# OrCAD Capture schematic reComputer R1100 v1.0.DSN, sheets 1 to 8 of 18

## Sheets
1 02 Block Diagram: rev: v1.0
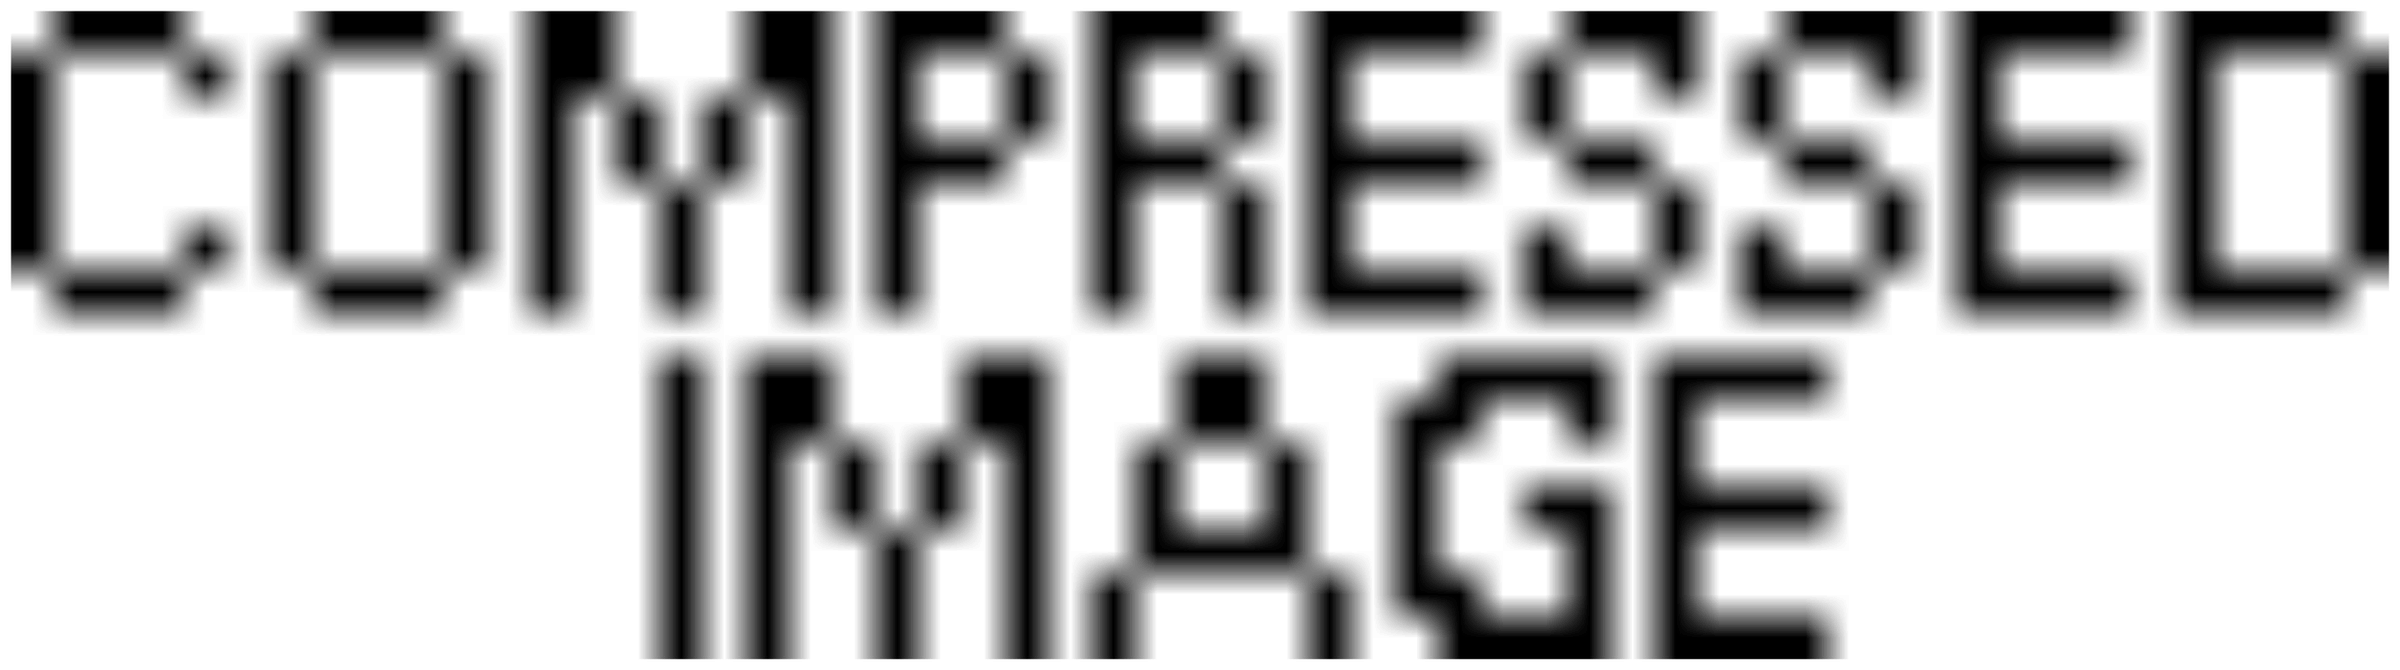
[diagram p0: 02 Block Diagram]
2 03 Power Block Diagram
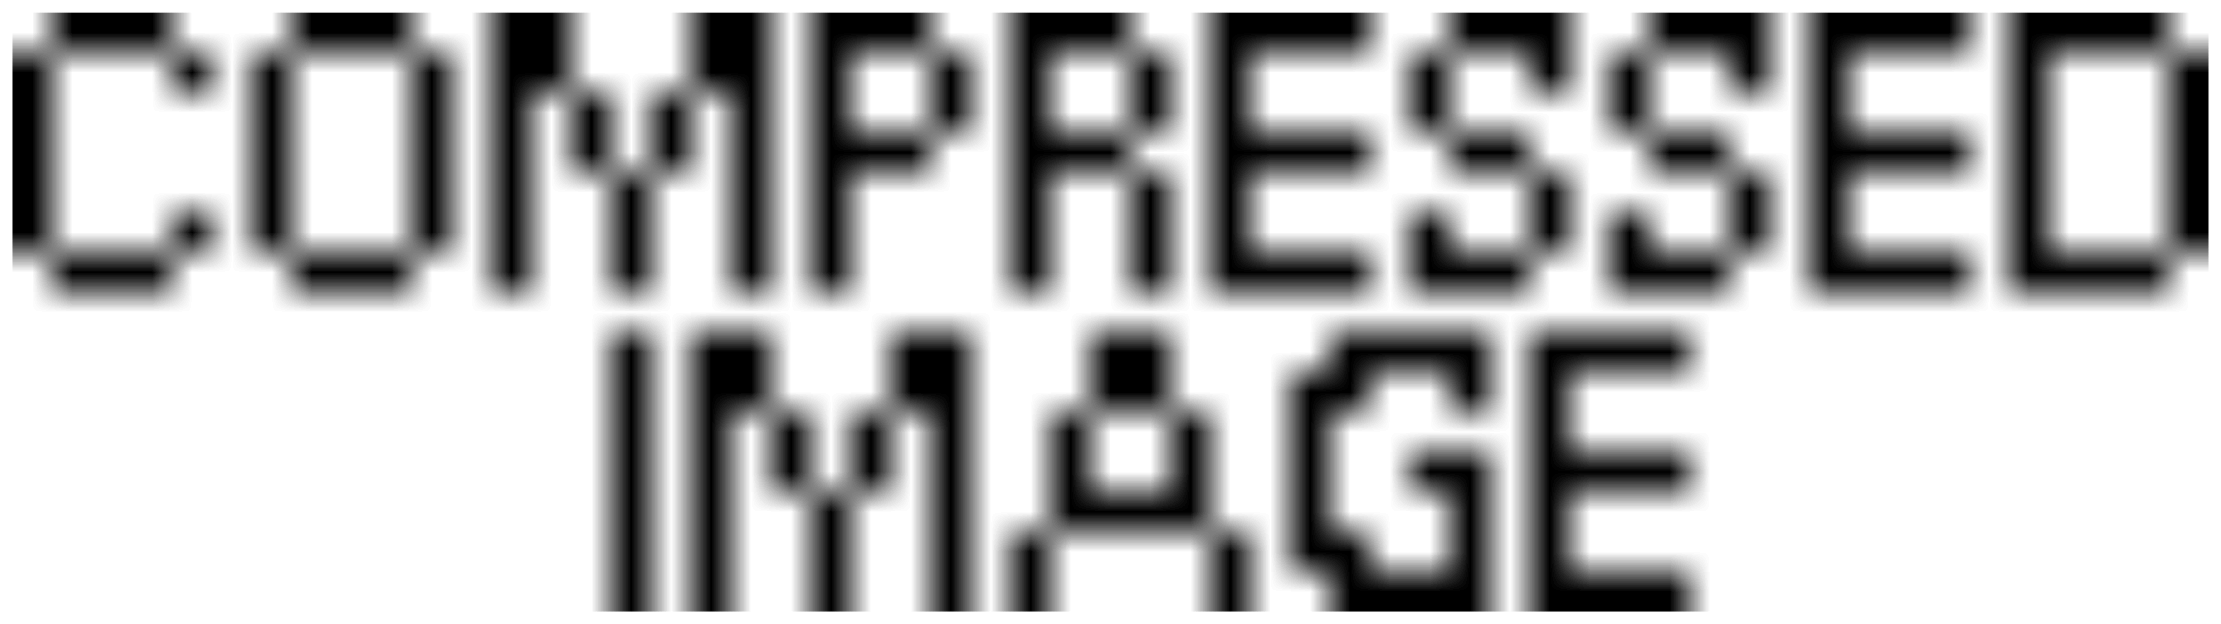
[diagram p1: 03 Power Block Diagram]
3 04 IIC TREE
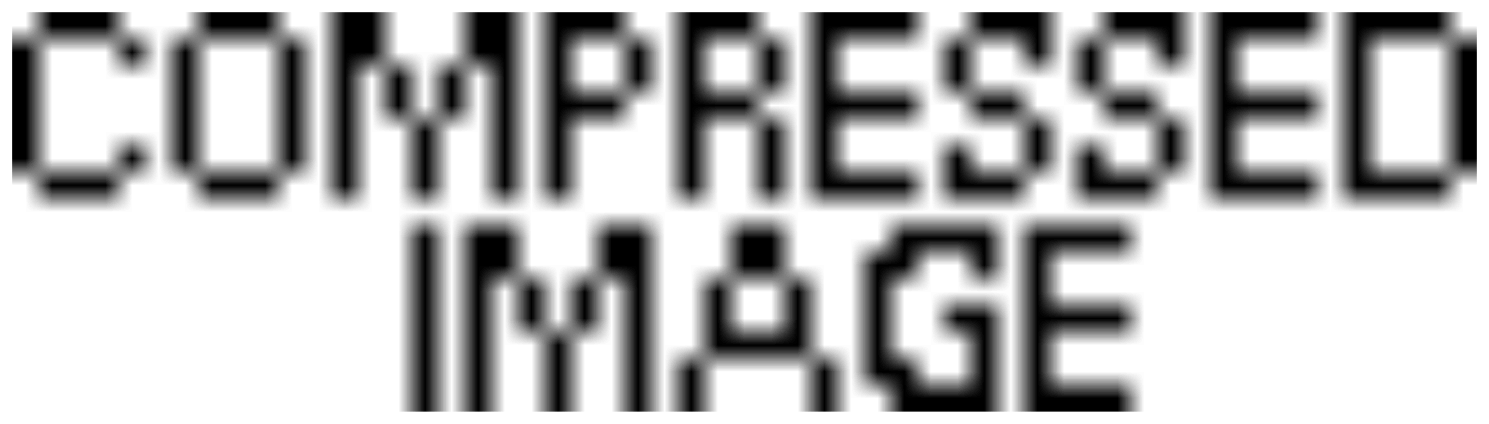
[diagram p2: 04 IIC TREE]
4 05 Power IN: size A3
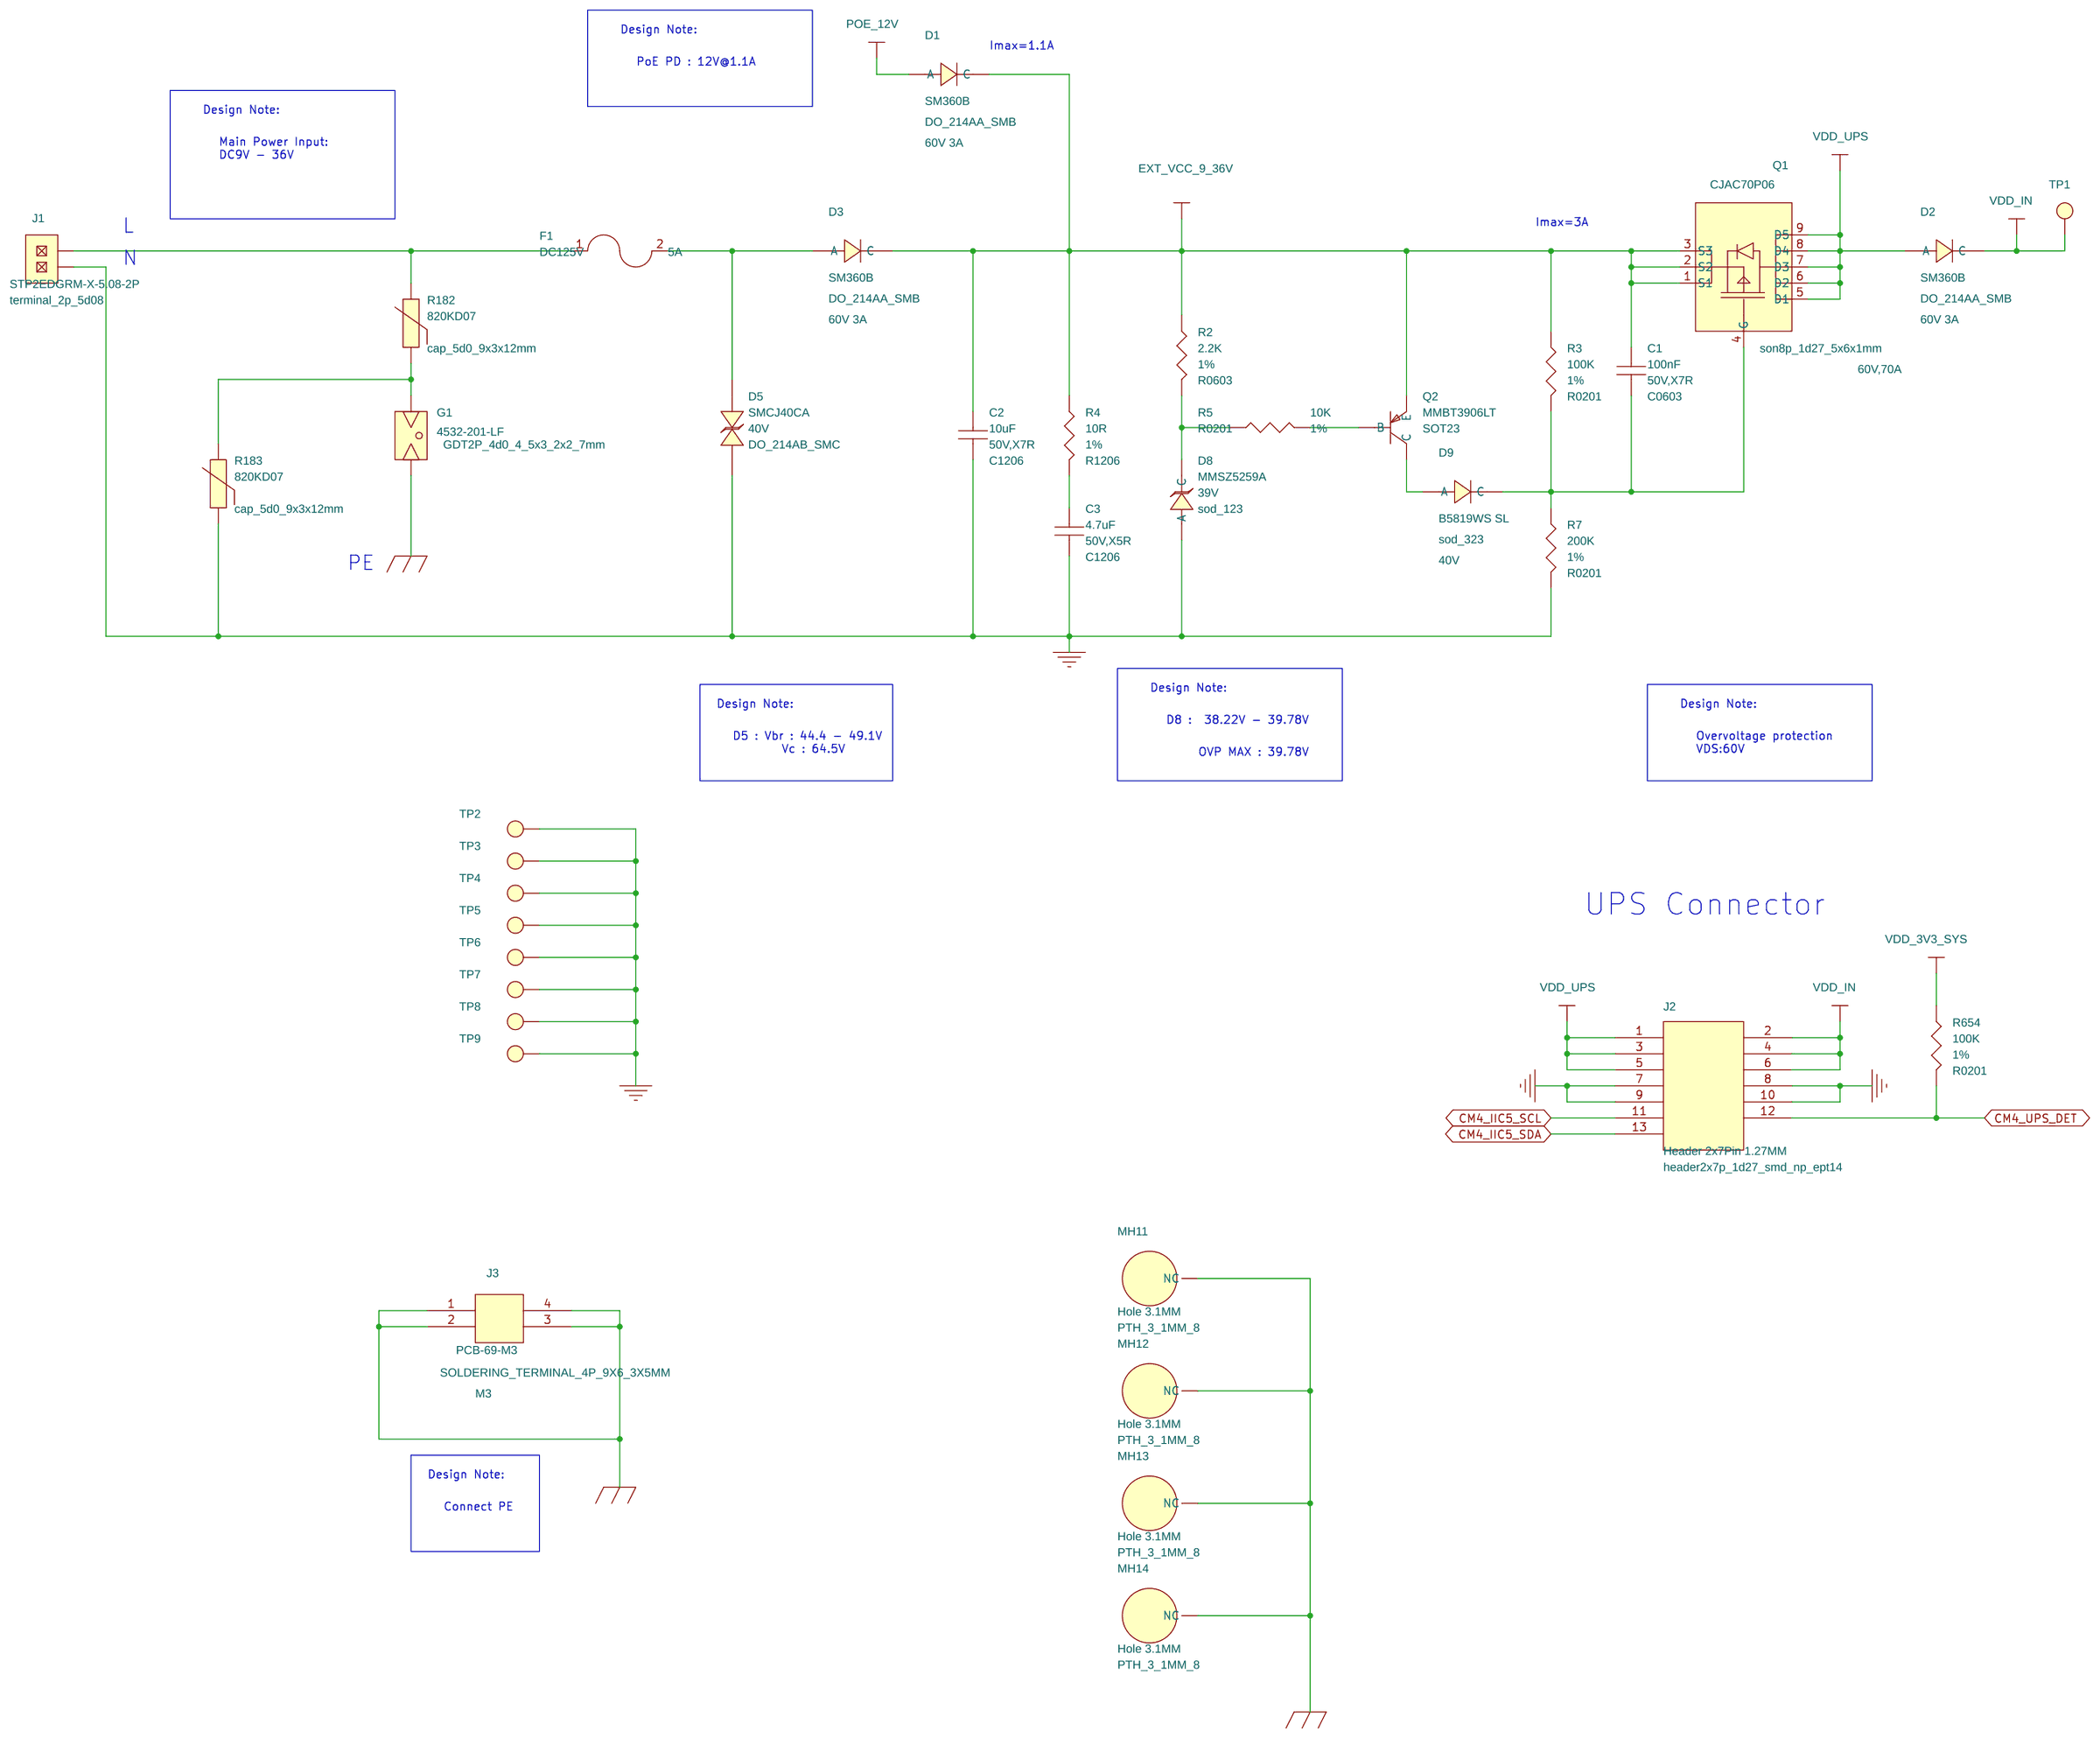
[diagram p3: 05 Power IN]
5 06 Power Management: size A3
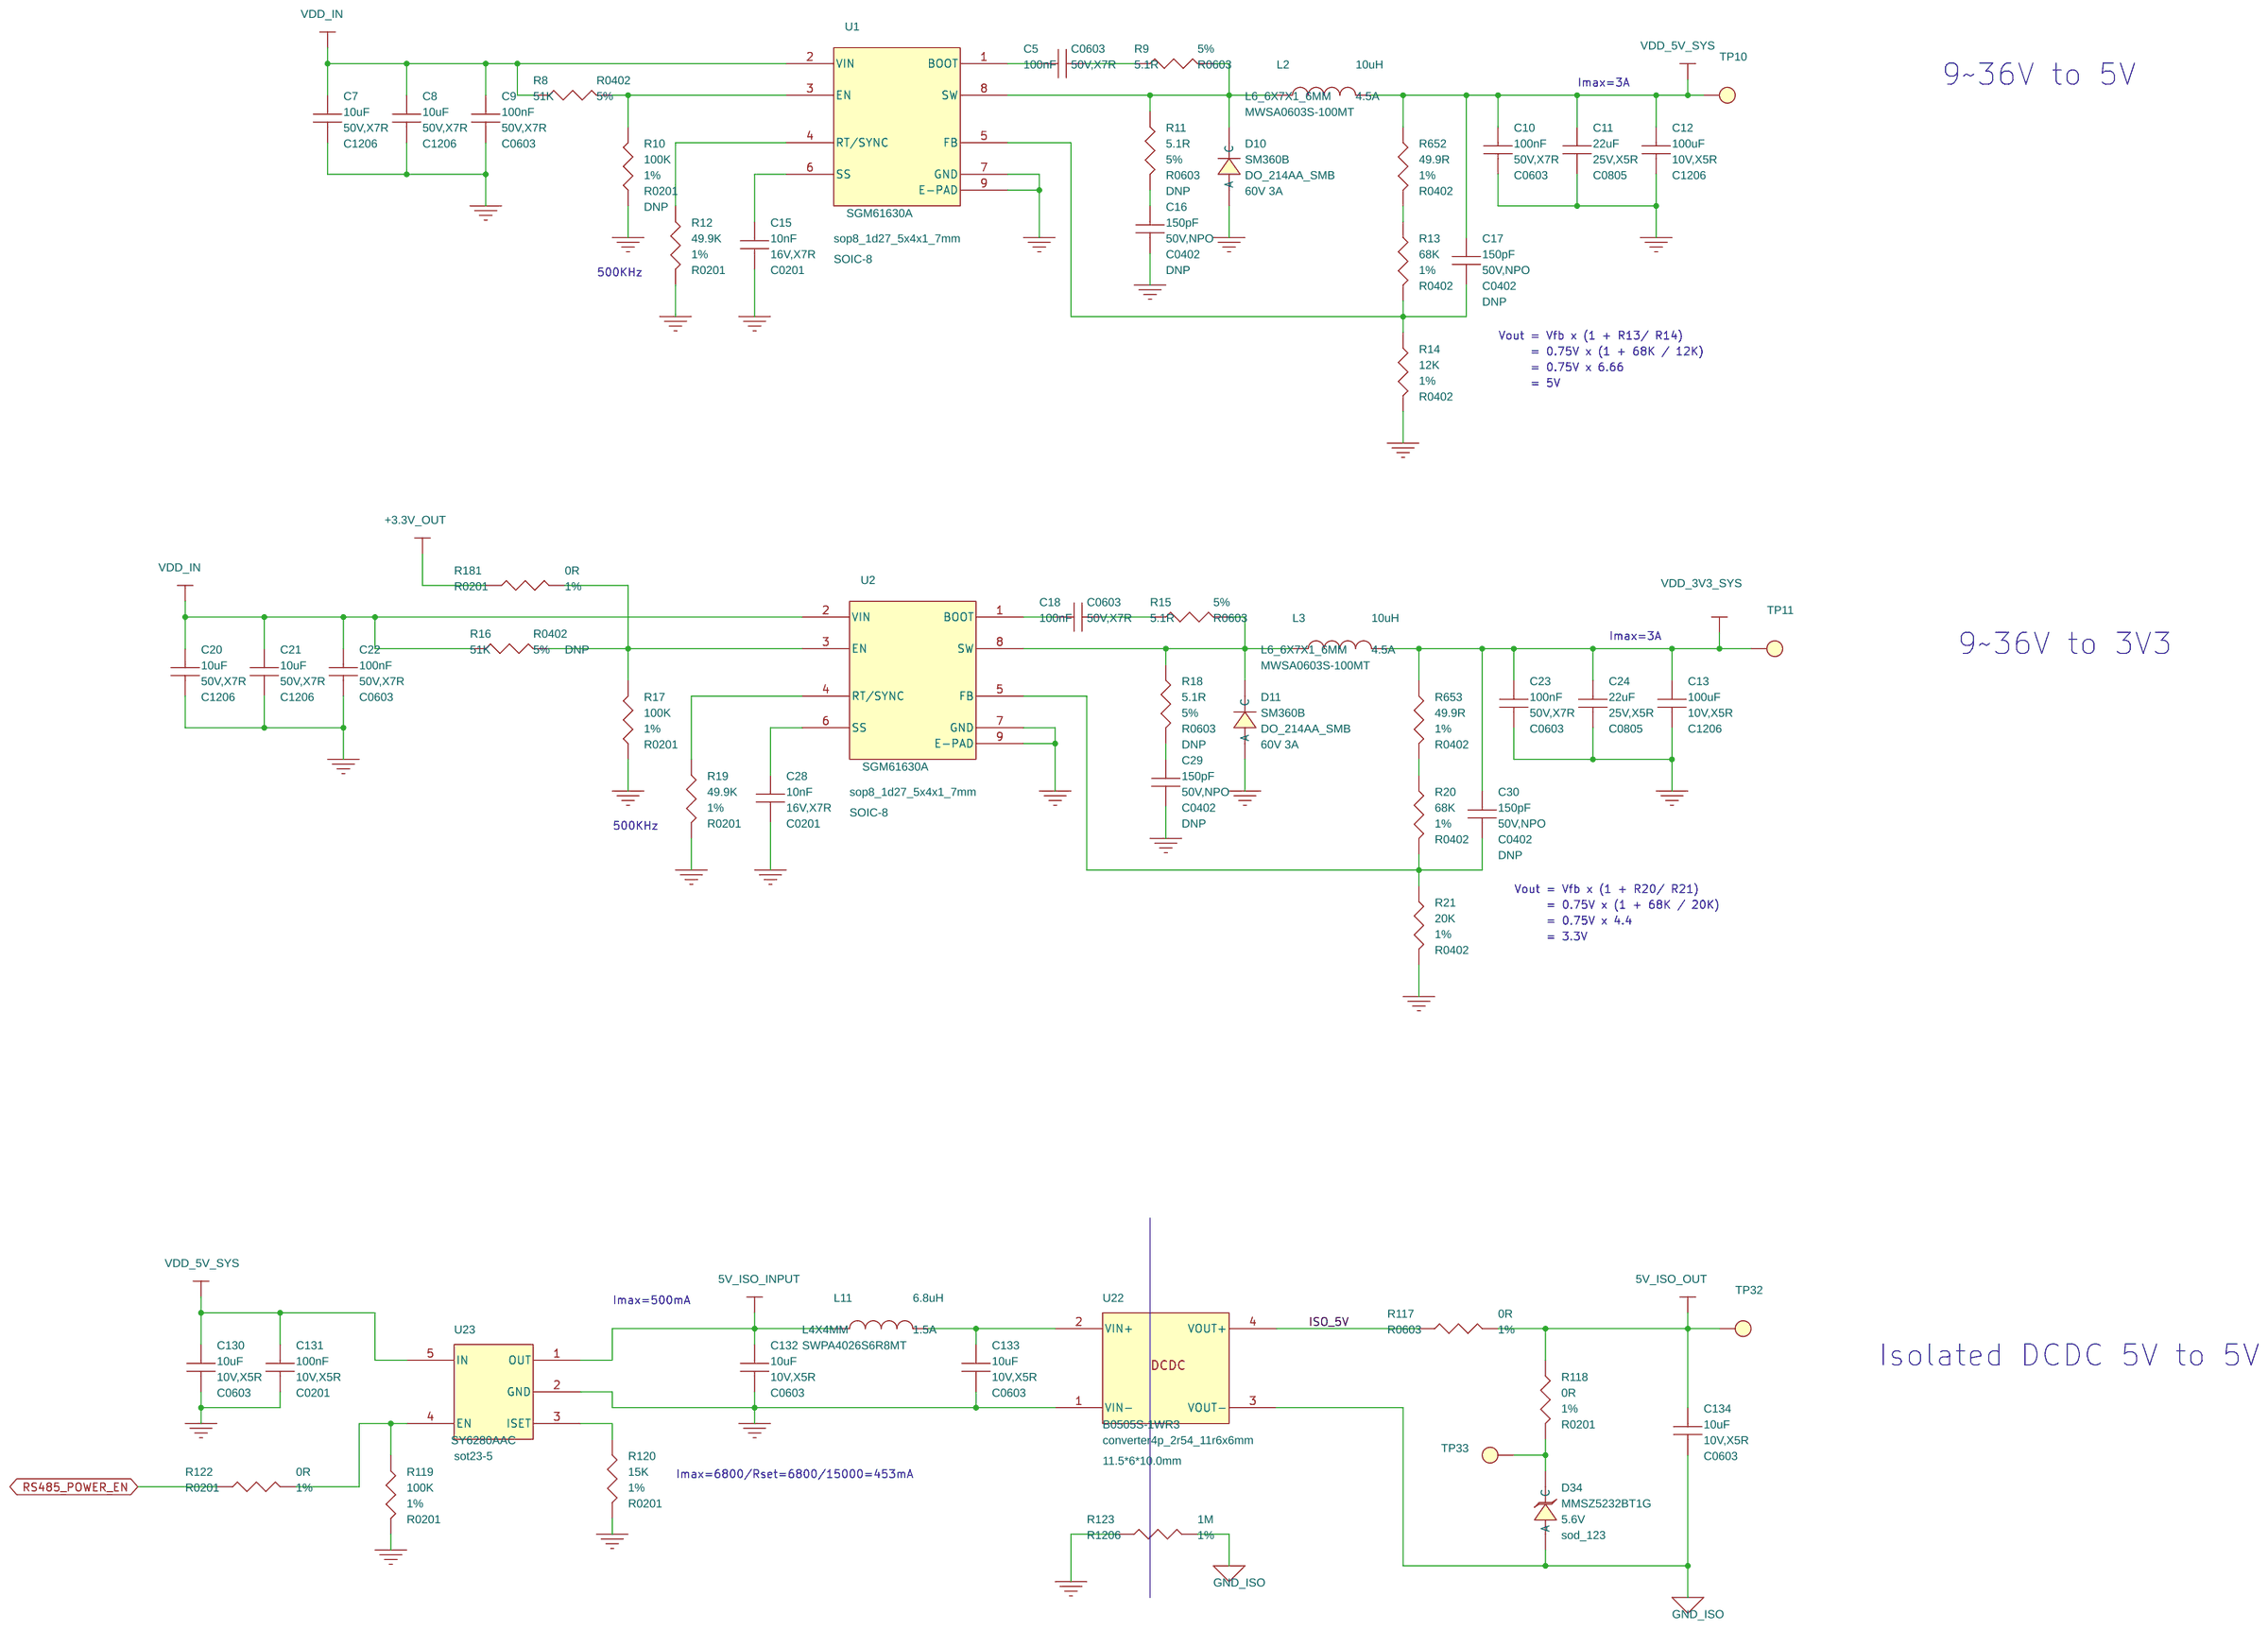
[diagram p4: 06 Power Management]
6 07 BTB-200PIN: size A3
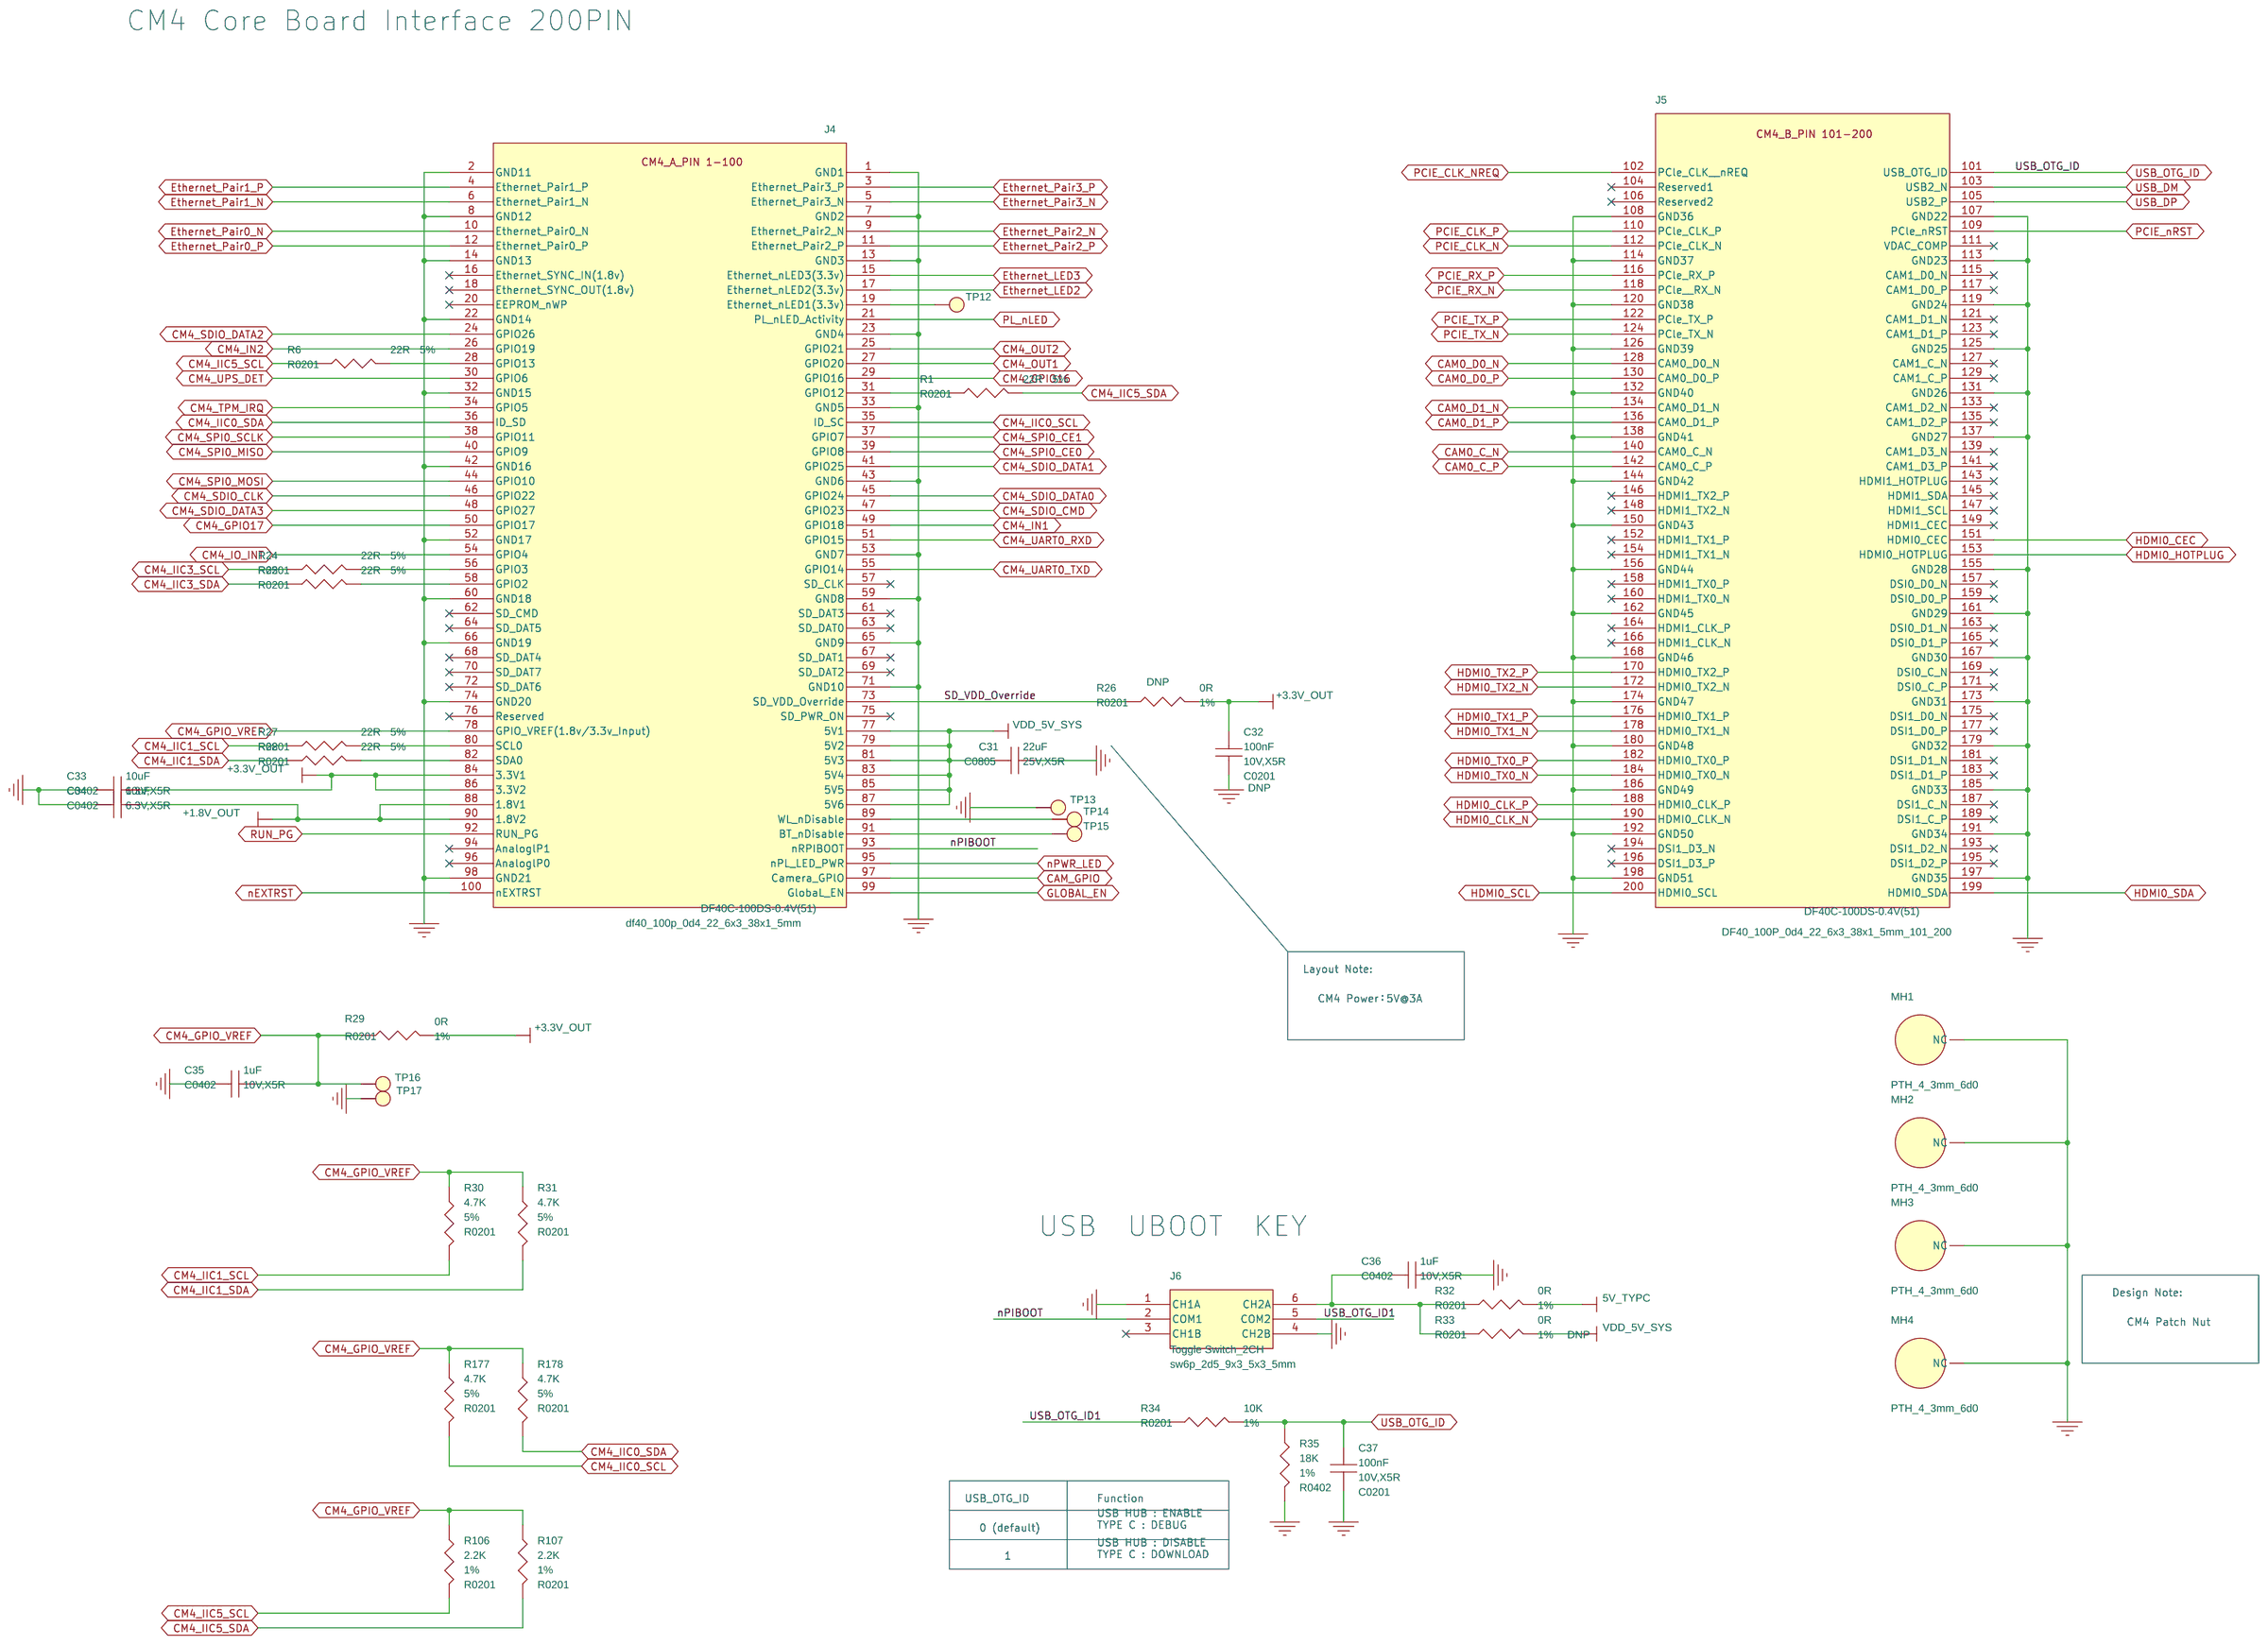
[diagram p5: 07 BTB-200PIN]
7 08 USB2.0 Switch & RST Button: size A3
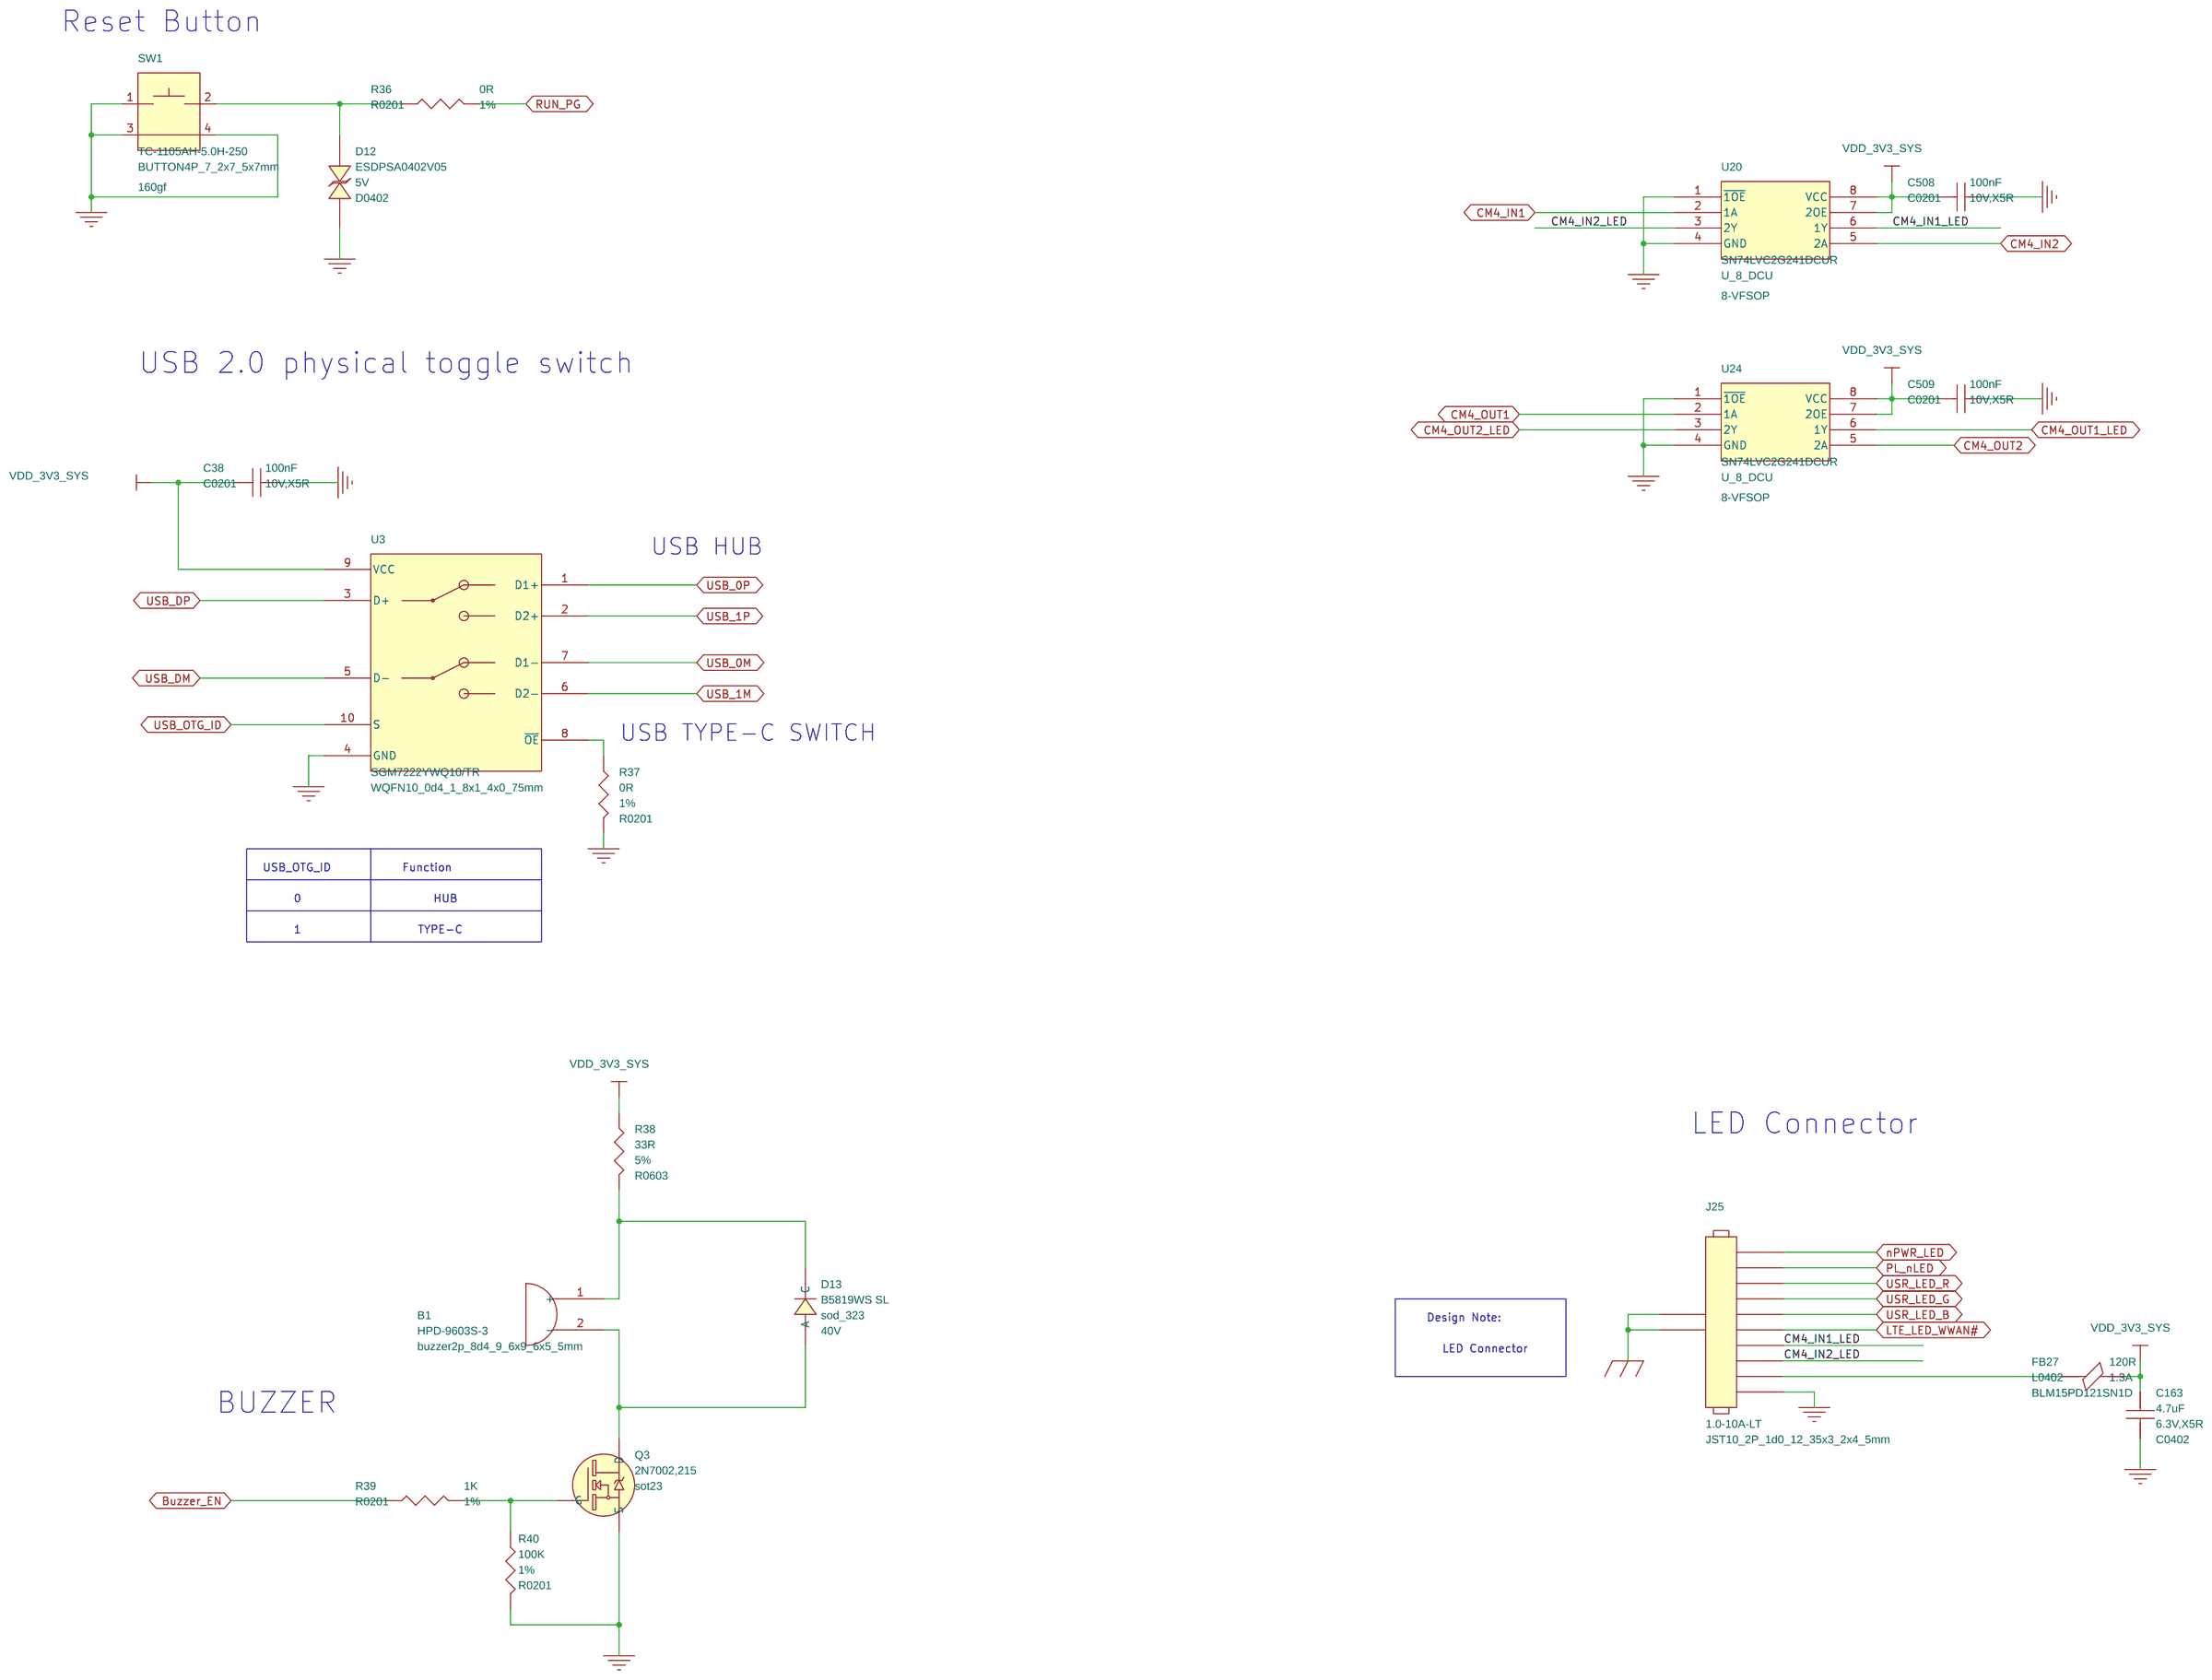
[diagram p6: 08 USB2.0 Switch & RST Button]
8 09 USB2.0 HUB1: size A3
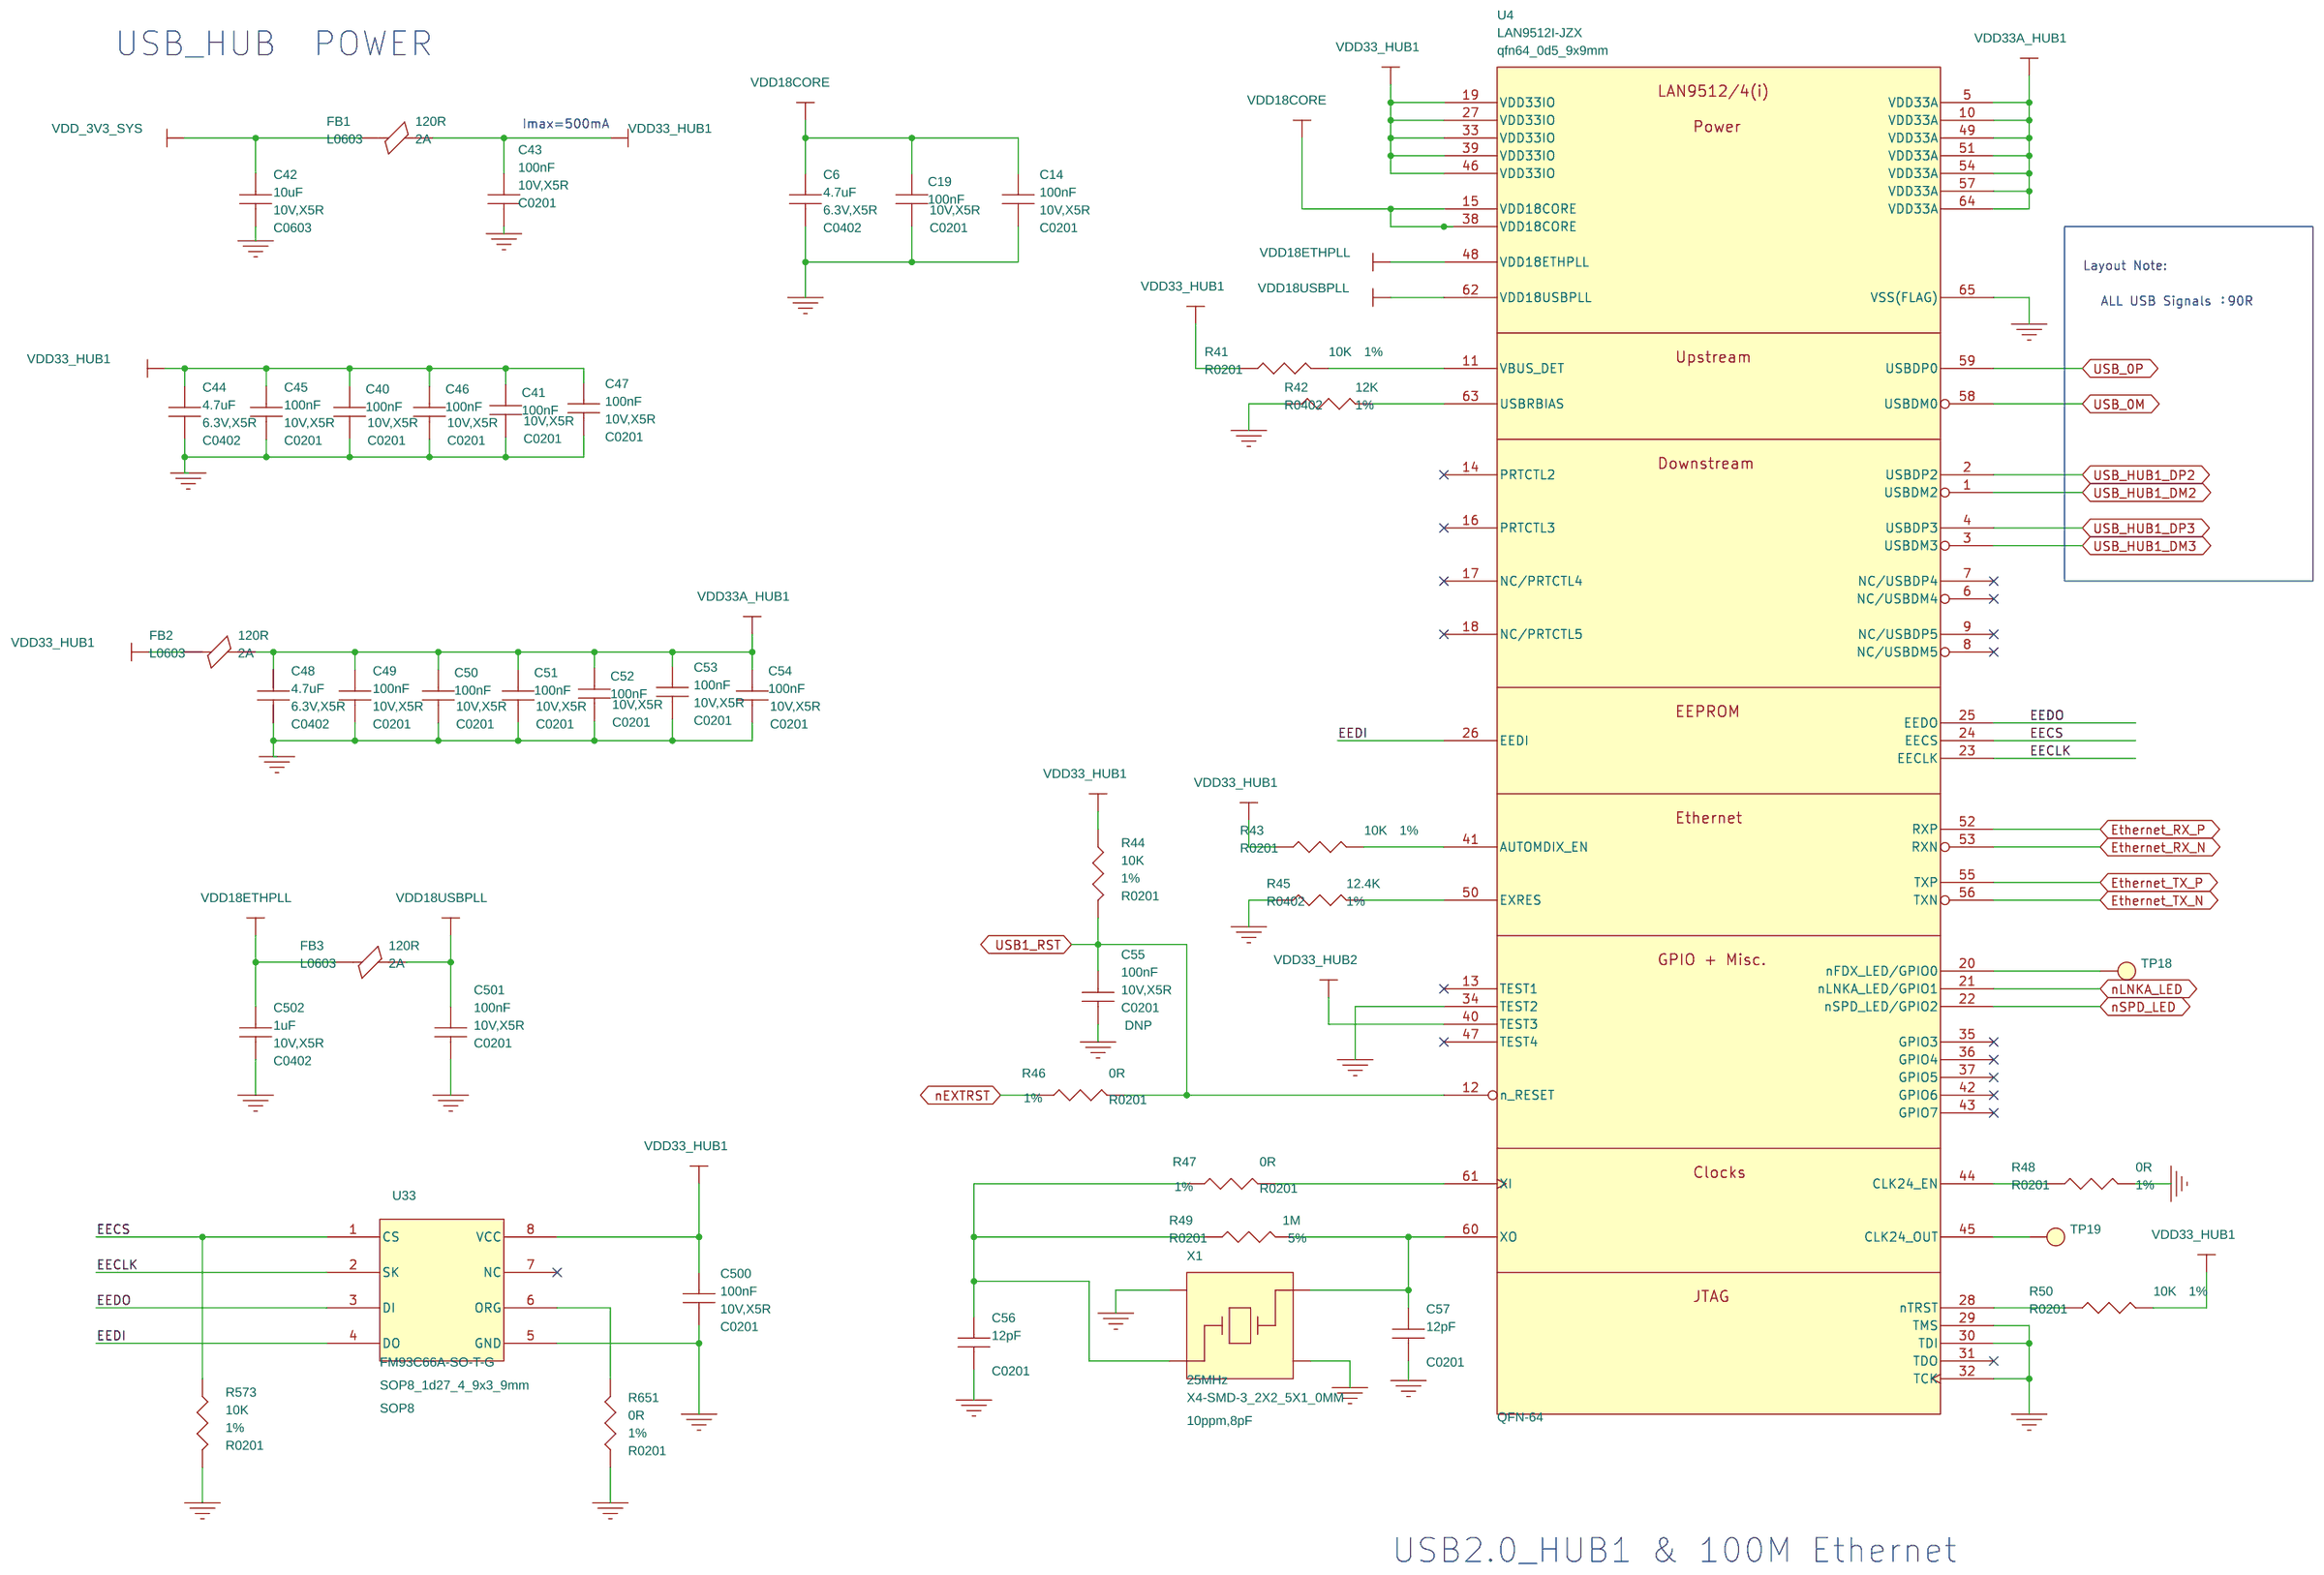
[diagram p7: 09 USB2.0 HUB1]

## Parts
sheet 05 Power IN
C1  100nF  [C0603]
C2  10uF  [C1206]
C3  4.7uF  [C1206]
D1  SM360B  [DO_214AA_SMB]
D2  SM360B  [DO_214AA_SMB]
D3  SM360B  [DO_214AA_SMB]
D5  SMCJ40CA  [DO_214AB_SMC]
D8  MMSZ5259A  [sod_123]
D9  B5819WS SL  [sod_323]
F1  5A  [FUSE2P_holder_9_73x5_03x3_81mm]
G1  4532-201-LF  [GDT2P_4d0_4_5x3_2x2_7mm]
J1  STP2EDGRM-X-5.08-2P  [terminal_2p_5d08]
J2  Header 2x7Pin 1.27MM  [header2x7p_1d27_smd_np_ept14]
J3  PCB-69-M3  [SOLDERING_TERMINAL_4P_9X6_3X5MM]
MH11  Hole 3.1MM  [PTH_3_1MM_8]
MH12  Hole 3.1MM  [PTH_3_1MM_8]
MH13  Hole 3.1MM  [PTH_3_1MM_8]
MH14  Hole 3.1MM  [PTH_3_1MM_8]
Q1  CJAC70P06  [son8p_1d27_5x6x1mm]
Q2  MMBT3906LT  [SOT23]
R2  2.2K  [R0603]
R3  100K  [R0201]
R4  10R  [R1206]
R5  10K  [R0201]
R7  200K  [R0201]
R182  820KD07  [cap_5d0_9x3x12mm]
R183  820KD07  [cap_5d0_9x3x12mm]
R654  100K  [R0201]
TP1  Test Point  [TP35S_SMD]
TP2  Test Point  [TP35S_SMD]
TP3  Test Point  [TP35S_SMD]
TP4  Test Point  [TP35S_SMD]
TP5  Test Point  [TP35S_SMD]
TP6  Test Point  [TP35S_SMD]
TP7  Test Point  [TP35S_SMD]
TP8  Test Point  [TP35S_SMD]
TP9  Test Point  [TP35S_SMD]
sheet 06 Power Management
C5  100nF  [C0603]
C7  10uF  [C1206]
C8  10uF  [C1206]
C9  100nF  [C0603]
C10  100nF  [C0603]
C11  22uF  [C0805]
C12  100uF  [C1206]
C13  100uF  [C1206]
C15  10nF  [C0201]
C16  150pF  [C0402]
C17  150pF  [C0402]
C18  100nF  [C0603]
C20  10uF  [C1206]
C21  10uF  [C1206]
C22  100nF  [C0603]
C23  100nF  [C0603]
C24  22uF  [C0805]
C28  10nF  [C0201]
C29  150pF  [C0402]
C30  150pF  [C0402]
C130  10uF  [C0603]
C131  100nF  [C0201]
C132  10uF  [C0603]
C133  10uF  [C0603]
C134  10uF  [C0603]
D10  SM360B  [DO_214AA_SMB]
D11  SM360B  [DO_214AA_SMB]
D34  MMSZ5232BT1G  [sod_123]
L2  10uH  [L6_6X7X1_6MM]
L3  10uH  [L6_6X7X1_6MM]
L11  6.8uH  [L4X4MM]
R8  51K  [R0402]
R9  5.1R  [R0603]
R10  100K  [R0201]
R11  5.1R  [R0603]
R12  49.9K  [R0201]
R13  68K  [R0402]
R14  12K  [R0402]
R15  5.1R  [R0603]
R16  51K  [R0402]
R17  100K  [R0201]
R18  5.1R  [R0603]
R19  49.9K  [R0201]
R20  68K  [R0402]
R21  20K  [R0402]
R117  0R  [R0603]
R118  0R  [R0201]
R119  100K  [R0201]
R120  15K  [R0201]
R122  0R  [R0201]
R123  1M  [R1206]
R181  0R  [R0201]
R652  49.9R  [R0402]
R653  49.9R  [R0402]
TP10  Test Point  [TP35S_SMD]
TP11  Test Point  [TP35S_SMD]
TP32  Test Point  [TP35S_SMD]
TP33  Test Point  [TP35S_SMD]
U1  SGM61630A  [sop8_1d27_5x4x1_7mm]
U2  SGM61630A  [sop8_1d27_5x4x1_7mm]
U22  B0505S-1WR3  [converter4p_2r54_11r6x6mm]
U23  SY6280AAC  [sot23-5]
sheet 07 BTB-200PIN
C31  22uF  [C0805]
C32  100nF  [C0201]
C33  10uF  [C0402]
C34  10uF  [C0402]
C35  1uF  [C0402]
C36  1uF  [C0402]
C37  100nF  [C0201]
J4  DF40C-100DS-0.4V(51)  [df40_100p_0d4_22_6x3_38x1_5mm]
J5  DF40C-100DS-0.4V(51)  [DF40_100P_0d4_22_6x3_38x1_5mm_101_200]
J6  Toggle Switch_2CH  [sw6p_2d5_9x3_5x3_5mm]
MH1  MHole  [PTH_4_3mm_6d0]
MH2  MHole  [PTH_4_3mm_6d0]
MH3  MHole  [PTH_4_3mm_6d0]
MH4  MHole  [PTH_4_3mm_6d0]
R1  22R  [R0201]
R6  22R  [R0201]
R24  22R  [R0201]
R25  22R  [R0201]
R26  0R  [R0201]
R27  22R  [R0201]
R28  22R  [R0201]
R29  0R  [R0201]
R30  4.7K  [R0201]
R31  4.7K  [R0201]
R32  0R  [R0201]
R33  0R  [R0201]
R34  10K  [R0201]
R35  18K  [R0402]
R106  2.2K  [R0201]
R107  2.2K  [R0201]
R177  4.7K  [R0201]
R178  4.7K  [R0201]
TP12  Test Point  [TP35S_SMD]
TP13  Test Point  [TP35S_SMD]
TP14  Test Point  [TP35S_SMD]
TP15  Test Point  [TP35S_SMD]
TP16  Test Point  [TP35S_SMD]
TP17  Test Point  [TP35S_SMD]
sheet 08 USB2.0 Switch & RST Button
B1  HPD-9603S-3  [buzzer2p_8d4_9_6x9_6x5_5mm]
C38  100nF  [C0201]
C163  4.7uF  [C0402]
C508  100nF  [C0201]
C509  100nF  [C0201]
D12  ESDPSA0402V05  [D0402]
D13  B5819WS SL  [sod_323]
FB27  120R  [L0402]
J25  1.0-10A-LT  [JST10_2P_1d0_12_35x3_2x4_5mm]
Q3  2N7002,215  [sot23]
R36  0R  [R0201]
R37  0R  [R0201]
R38  33R  [R0603]
R39  1K  [R0201]
R40  100K  [R0201]
SW1  TC-1105AH-5.0H-250  [BUTTON4P_7_2x7_5x7mm]
U3  SGM7222YWQ10/TR  [WQFN10_0d4_1_8x1_4x0_75mm]
U20  SN74LVC2G241DCUR  [U_8_DCU]
U24  SN74LVC2G241DCUR  [U_8_DCU]
sheet 09 USB2.0 HUB1
C6  4.7uF  [C0402]
C14  100nF  [C0201]
C19  100nF  [C0201]
C40  100nF  [C0201]
C41  100nF  [C0201]
C42  10uF  [C0603]
C43  100nF  [C0201]
C44  4.7uF  [C0402]
C45  100nF  [C0201]
C46  100nF  [C0201]
C47  100nF  [C0201]
C48  4.7uF  [C0402]
C49  100nF  [C0201]
C50  100nF  [C0201]
C51  100nF  [C0201]
C52  100nF  [C0201]
C53  100nF  [C0201]
C54  100nF  [C0201]
C55  100nF  [C0201]
C56  12pF  [C0201]
C57  12pF  [C0201]
C500  100nF  [C0201]
C501  100nF  [C0201]
C502  1uF  [C0402]
FB1  120R  [L0603]
FB2  120R  [L0603]
FB3  120R  [L0603]
R41  10K  [R0201]
R42  12K  [R0402]
R43  10K  [R0201]
R44  10K  [R0201]
R45  12.4K  [R0402]
R46  0R  [R0201]
R47  0R  [R0201]
R48  0R  [R0201]
R49  1M  [R0201]
R50  10K  [R0201]
R573  10K  [R0201]
R651  0R  [R0201]
TP18  Test Point  [TP35S_SMD]
TP19  Test Point  [TP35S_SMD]
U4  LAN9512I-JZX  [qfn64_0d5_9x9mm]
U33  FM93C66A-SO-T-G  [SOP8_1d27_4_9x3_9mm]
X1  25MHz  [X4-SMD-3_2X2_5X1_0MM]

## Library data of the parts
C1 C5 C9 C10 C18 C22 C23 = CC: SMD CAP Ceramic 100nF-50V-10%-X7R;0603; Manufacturer: YAGEO; Manufacturer Part Number: CC0603KRX7R9BB104; PN: 302010138; Part Type: Ceramic; Rating: 50V,X7R; Status: BeagleBone Carrier Board; Temperature: -55°C to 125°C
C2 = CC: SMD CAP Ceramic 10UF-50V-10%-X7R;1206; Manufacturer: Samsung; Manufacturer Part Number: CL31B106KBHNNNE; PN: 302012419; Rating: 50V,X7R; Status: reTerminal DM; Temperature: -55°C to 125°C
C3 = CC: SMD CAP Ceramic 4.7uF-50V-10%-X5R;1206; Manufacturer: YAGEO; Manufacturer Part Number: CC1206KKX5R9BB475; PN: 302010243; Part Type: Ceramic; Rating: 50V,X5R; Status: BeagleBone Carrier Board; Temperature: -55°C to 85°C
D1-D3 D10 D11 = D: SMD Diode Schottky 60V-3A;SMB; PN: TMP-507; Package Size: SMB; Rating: 60V 3A; Status: reComputer CM4 R101; Temperature: -50°C  to 150°C
D5 = DIODE_TVS_BI-DIR: SMD Diode TVS 40V-1.5kW;SMC; Manufacturer: 君耀; Manufacturer Part Number: SMCJ40CA/TR7; PN: 304051164; Package Size: SMC; Rating: 40V; Status: reServer Jetson Orin; Temperature: -55°C to 150°C
D8 = DIODE_TVS: SMD Diode Zener 39V-500mW;SOD-123; Manufacturer: PANJIT; Manufacturer Part Number: MMSZ5259A_R1_00001; PN: 304030729; Package Size: SOD-123; Rating: 39V; Status: reServer Jetson Orin; Temperature: -50°C to 150°C
D9 D13 = D: SMD Diode Schottky 40V-1A;SOD-323; Manufacturer: CJ; PN: 304011053; Part Type: Schottky Diode; Rating: 40V; Status: reTerminal DM
F1 = Fuse: SMD Fuseholder with Fuse-5A;2P-L9.73*W5.03*H3.81mm; Manufacturer: REOMAX; Manufacturer Part Number: 0154R425_1808 STE1500; PN: 307020350; Rating: DC125V; Status: reTerminal DM; Temperature: -55°C to 125°C
G1 = gdt_2p: SMD Gas Discharge Tube 100V 2KA  2 Electrodes;; Manufacturer: 君耀; PN: TMP-523; Package Size: 4_5x3_2x2_7mm; Rating: 100V,2KA; Status: reComputer CM4 R101; Temperature: -40°C to 85°C
J1 = Header_1x2: DIP Female Screw Terminal-Green;1*2P-5.08-90D; Manufacturer: 思拓展; PN: 320112030; Package Size: 1*2P-5.08mm; Status: reComputer R1002; Temperature: -40°C to 105°C
J2 = Header_2x7_13P: SMD Black Male Header VERT;With Positioning,Without Pin14;2*7P-1.27-5.5-4.0mm; Manufacturer: 思拓展; Manufacturer Part Number: SF-PH-127-0030-2*7-K14-D; PN: 320021939; Package Size: 2*7P-1.27-5.5-4.0mm; Status: reComputer Industrial J201; Temperature: -40°C to 105°C
J3 = SOLDERING_TERMINAL_4P: DIP PCB Soldering Terminal M3, 4P; PN: TMP-513; Package Size: 9.0*6.3*9.0mm; Rating: M3; Status: reComputer CM4 R101; Temperature: '-40°C to 85°C
MH11-MH14 = MHole: MISC, Mhole, Hole 3.1MM, DIP,; PN: TMP-525; Package Size: D3.1 mm; Status: reComputer CM4 R101; Temperature: -40°C to 85°C
Q1 = PMOS_9P: SMD MOSFET P-CH 60V-70A;PDFNWB5*6-8L; Manufacturer: CJ; PN: 305020497; Package Size: PDFNWB5*6-8L; Rating: 60V,70A; Status: reTerminal Plus; Temperature: -55°C to 150°C
Q2 = PNP: SMD Transistors PNP 40V-200mA;SOT-23; Manufacturer: ON; Manufacturer Part Number: MMBT3906LT3G; PN: 305020002; Priority: A; Rating: 40V,200mA; Status: reComputer J401; Temperature: -55°C to 150°C
R2 = R: SMD RES 2.2K-1%-1/10W;0603; Manufacturer: YAGEO; Manufacturer Part Number: RC0603FR-072K2L; PN: 301010200; Package Size: 0603; Rating: 1%; Temperature: -55°C to 155°C
R3 R17 R654 = R: SMD RES 100K-±1%-1/20W;0201; Manufacturer: YAGEO; Manufacturer Part Number: RC0201FR-07100KL; PN: 301010765; Package Size: 0201; Part Type: RES; Rating: 1%; Status: LR1110; Temperature: -55°C to 125°C
R4 = R: SMD RES;10R-1%-1/4W-1206; Manufacturer: YAGEO; Manufacturer Part Number: RC1206FR-0710RL; PN: 301010528; Part Type: RES; Rating: 1%; Status: Mini-Gateway; Temperature: -55°C to 155°C
R5 = R: SMD RES 10K-±1%-1/20W;0201; Manufacturer: YAGEO; Manufacturer Part Number: RC0201FR-0710KL; PN: 301010526; Package Size: 0201; Part Type: RES; Rating: 1%; Status: BeagleBone AI TDA4VM; Temperature: -55°C to 125°C
R7 = R: SMD RES 200K-1%-1/20W;0201; Manufacturer: YAGEO; Manufacturer Part Number: RC0201FR-07200KL; PN: 301011319; Package Size: 0201; Rating: 1%; Status: BeagleV-Ahead; Temperature: -55°C to 125°C
R182 R183 = VDR: DIP RES Varistor 74V-90V;P=5mm-D=7mm; Manufacturer: YAGEO; PN: 314130247; Status: Sensecap one; Temperature: -40°C to 105°C
TP1-TP19 TP32 = Test_Point: Test Point;TP35S_SMD; CLASS: DISCRETE; Company Part Status: Mini-Gateway; Status: Mini-Gateway
C7 C8 C20 C21 = CC: SMD CAP Ceramic 10UF-50V-10%-X7R;1206; Manufacturer: Samsung; Manufacturer Part Number: CL31B106KBHNNNE; PN: 302012419; Part Type: Ceramic; Rating: 50V,X7R; Status: reTerminal DM; Temperature: -55°C to 125°C
C11 C24 C31 = CC: SMD CAP Ceramic 22uF-25V-20%-X5R;0805; Manufacturer: SAMSUNG; Manufacturer Part Number: CL21A226MAYNNNE; PN: 302013260; Package Size: 0805; Rating: 25V,X5R; Status: reServer Jetson Orin; Temperature: -55°C to 85°C
C12 C13 = CC: SMD CAP Ceramic 100uF-10V-20%-X5R;1206; Manufacturer: Murata; Manufacturer Part Number: GRM31CR61A107ME05L; PN: 302013339; Package Size: 1206; Rating: 10V,X5R; Status: reRouter CM4 PoE; Temperature: -55°C to 85°C
C15 C28 = CC: SMD CAP Ceramic 10nF-16V-10%-X7R;0201; Manufacturer: YAGEO; Manufacturer Part Number: CC0201KRX7R7BB103; PN: 302010431; Part Type: Ceramic; Rating: 16V,X7R; Status: BeagleBone AI TDA4VM; Temperature: -55°C to 125°C
C16 C17 C29 C30 = CC: SMD CAP Ceramic 150pF-50V-5%-NPO;0402; ASSY: DNP; Manufacturer: YAGEO; Manufacturer Part Number: CC0402JRNPO9BN151; PN: 302010015; Part Type: Ceramic; Priority: A; Rating: 50V,NPO; Status: reComputer Industrial J2031; Temperature: -55°C to 125°C
C130 C132-C134 = CC: SMD CAP Ceramic 10uF-10V-10%-X5R;0603; Manufacturer: YAGEO; Manufacturer Part Number: CC0603KRX5R6BB106; PN: 302010103; Part Type: Ceramic; Rating: 10V,X5R; SIGNAL_MODEL: DEFAULT_CAPACITOR_4.7e+06pF_1_2; Status: BeagleBone Carrier Board; Temperature: -55°C to 85°C
C14 C19 C37 C38 C40 C41 C43 C45-C47 C49-C54 C131 C500 C501 C508 C509 = CC: SMD CAP Ceramic 100nF-10V-10%-X5R;0201; CLASS: DISCRETE; Company Part Status: BeagleBone Carrier Board; Dielectric Type: Ceramic; Manufacturer: YAGEO; Manufacturer PN: CC0402KRX7R8BB104; Manufacturer Part Number: CC0201KRX5R6BB104; PN: 302010271; Package Size: 0201; Part Type: Ceramic; Rating: 10V,X5R; SIGNAL_MODEL: DEFAULT_CAPACITOR_100000pF_1_2; Status: ODYSSEY-i.MX8M; Temperature: -55°C to 85°C; Temperature Coefficient: X7R; Tolerance: 10%
D34 = DIODE_TVS: SMD Diode Zener 5.6V-500mW;SOD-123; Manufacturer: ON; PN: 304030710; Part Type: Zener Diode; Rating: 5.6V; Status: reTerminal DM
L2 L3 = L: SMD Inductor 10uH-20%-4.5A;2P-L6.6*W7.0*H3.0mm; Manufacturer: Sunlord; Manufacturer Part Number: MWSA0603S-100MT; PN: 303011869; Rating: 4.5A; Status: RK3566_HA; Temperature: -40°C to 125°C
L11 = L: SMD Inductor 6.8uH-20%-1.5A;L4.0xW4.0xH2.6mm; Manufacturer: Sunlord; Manufacturer Part Number: SWPA4026S6R8MT; PN: 303011409; Part Type: Inductor; Rating: 1.5A; Status: Zola_Gateway; Temperature: -40°C to 125°C
R8 = R: SMD RES 51K-5%-1/16W;0402; Manufacturer: YAGEO; Manufacturer Part Number: RC0402JR-0751KL; PN: 301010027; Part Type: RES; Rating: 5%; Temperature: -55°C to 155°C
R9 R15 = R: SMD RES 5.1R-5%-1/10W;0603; Manufacturer: YAGEO; Manufacturer Part Number: RC0603JR-075R1L; PN: 301012675; Package Size: 0603; Rating: 5%; Status: Jetson-20-2; Temperature: -55°C to 155°C
R10 = R: SMD RES 100K-±1%-1/20W;0201; ASSY: DNP; Manufacturer: YAGEO; Manufacturer Part Number: RC0201FR-07100KL; PN: 301010765; Package Size: 0201; Part Type: RES; Rating: 1%; Status: LR1110; Temperature: -55°C to 125°C
R11 R18 = R: SMD RES 5.1R-5%-1/10W;0603; ASSY: DNP; Manufacturer: YAGEO; Manufacturer Part Number: RC0603JR-075R1L; PN: 301012675; Package Size: 0603; Rating: 5%; Status: Jetson-20-2; Temperature: -55°C to 155°C
R12 R19 = R: SMD RES 49.9K-1%-1/20W;0201; Manufacturer: YAGEO; Manufacturer Part Number: RC0201FR-0749K9L; PN: 301012644; Package Size: 0201; Rating: 1%; Status: SOM62; Temperature: -55°C to 125°C
R13 R20 = R: SMD RES 68K-1%-1/10W;0402; Manufacturer: YAGEO; Manufacturer Part Number: RC0402FR-0768KL; PN: 301010740; Package Size: 0402; Rating: 1%; Status: R2; Temperature: -55°C to 155°C
R14 R42 = R: SMD RES 12K-1%-1/16W;0402; Manufacturer: YAGEO; Manufacturer Part Number: RC0402FR-0712KL; PN: 301010736; Package Size: 0402; Rating: 1%; Status: BeagleBone Carrier Board; Temperature: -55°C to 155°C
R16 = R: SMD RES 51K-5%-1/16W;0402; ASSY: DNP; Manufacturer: YAGEO; Manufacturer Part Number: RC0402JR-0751KL; PN: 301010027; Part Type: RES; Rating: 5%; Temperature: -55°C to 155°C
R21 = R: SMD RES 20K-1%-1/16W;0402; Manufacturer: YAGEO; Manufacturer Part Number: RC0402FR-0720KL; PN: 301010072; Package Size: 0402; Rating: 1%; Status: Grove Base Cape for PocketBeagle; Temperature: -55°C to 155°C
R117 = R: SMD RES 0R-1%-1/10W;0603; Manufacturer: YAGEO; Manufacturer Part Number: RC0603FR-070RL; PN: 301012029; Part Type: RES; Rating: 1%; Status: BBG Gateway; Temperature: -55°C to 155°C
R32 R36 R37 R118 R122 R181 = R: SMD RES 0R-±1%-1/20W;0201; Manufacturer: YAGEO; Manufacturer Part Number: RC0201FR-070RL; PN: 301010525; Package Size: 0201; Part Type: RES; Rating: 1%; Status: BeagleBone AI TDA4VM; Temperature: -55°C to 125°C; Datasheet: Y:\01_Cadence_Library\05_Datasheet\301010000_YAGEO_RC0402JR-070RL_Datasheet.pdf
R40 R119 = R: SMD RES 100K-±1%-1/20W;0201; CLASS: DISCRETE; Company Part Status: BeagleBone Carrier Board; Manufacturer: YAGEO; Manufacturer PN: RC0402FR-07100KL; Manufacturer Part Number: RC0201FR-07100KL; PN: 301010765; Package Size: 0201; Part Type: RES; Rated Power: 1/16W; Rating: 1%; Status: LR1110; Temperature: -55°C to 125°C
R120 = R: SMD RES 15K-1%-1/20W;0201; Manufacturer: YAGEO; Manufacturer Part Number: RC0201FR-0715KL; PN: 301012913; Package Size: 0201; Part Type: RES; Rating: 1%; Status: AM62_OSM; Temperature: -55°C to 125°C
R123 = R: SMD RES 1M-1%-1/4W;1206; Manufacturer: YAGEO; Manufacturer Part Number: RC1206FR-071ML; PN: 301010410; Part Type: RES; Rating: 1%; Status: Sensecap Gateway V1; Temperature: -55°C to 155°C
R652 R653 = R: SMD RES 49.9R-1%-1/16W;0402; Manufacturer: YAGEO; Manufacturer Part Number: RC0402FR-0749R9L; PN: 301010041; Package Size: 0402; Rating: 1%; Status: BeagleBone Carrier Board; Temperature: -55°C to 155°C
TP33 = Test_Point: Test Point;TP35S_SMD; Status: Mini-Gateway
U1 U2 = SGM61630A: SMD IC DCDC Buck, 4.3 to 60V Input, SOIC-8; PN: TMP-510; Package Size: SOIC-8; Rating: 3A; Status: reComputer CM4 R101; Temperature: -40°C to 125°C
U22 = Isolate_DCDC: DIP Isolated DCDC;5V to 5V,1500VDC/min,1W;4P-2.54mm-L11.50*W6.00*H10.0mm; Manufacturer: 海凌科电子; PN: TMP-757; Package Size: 11.5*6*10.0mm; Rating: 1W; Status: reComputer R1100; Temperature: -40°C to 85°C
U23 = SY6280: SMD IC PMIC;SOT23-5; Manufacturer: Silergy; PN: 310030260; Part Type: Power Switch; Status: R2
C32 C55 = CC: SMD CAP Ceramic 100nF-10V-10%-X5R;0201; ASSY: DNP; CLASS: DISCRETE; Company Part Status: BeagleBone Carrier Board; Dielectric Type: Ceramic; Manufacturer: YAGEO; Manufacturer PN: CC0402KRX7R8BB104; Manufacturer Part Number: CC0201KRX5R6BB104; PN: 302010271; Package Size: 0201; Part Type: Ceramic; Rating: 10V,X5R; SIGNAL_MODEL: DEFAULT_CAPACITOR_100000pF_1_2; Status: ODYSSEY-i.MX8M; Temperature: -55°C to 85°C; Temperature Coefficient: X7R; Tolerance: 10%
C33 C34 = CC: SMD CAP Ceramic 10uF-6.3V-20%-X5R;0402; CLASS: DISCRETE; Company Part Status: ST; Dielectric Type: Ceramic; Manufacturer: YAGEO; Manufacturer PN: CC0402MRX5R5BB106; Manufacturer Part Number: CC0402MRX5R5BB106; PN: 302010053; Package Size: 0402; Part Type: Ceramic; Priority: A; Rating: 6.3V,X5R; Status: ST; Temperature: -55°C to 85°C; Tolerance: 20%
C35 C36 = CC: SMD CAP Ceramic 1uF-10V-10%-X5R;0402; CLASS: DISCRETE; Company Part Status: BeagleBone Carrier Board; Dielectric Type: Ceramic; Manufacturer: YAGEO; Manufacturer PN: CC0402KRX5R6BB105; Manufacturer Part Number: CC0402KRX5R6BB105; PN: 302010040; Package Size: 0402; Part Type: Ceramic; Rating: 10V,X5R; SIGNAL_MODEL: DEFAULT_CAPACITOR_1e+06pF_1_2; Status: BeagleBone Carrier Board; Temperature: -55°C to 85°C; Temperature Coefficient: X5R; Tolerance: 10%
J4 = CM4_CON_A: SMD BTB Male CONN 2*50PIN;L22.6*W3.38*H1.45MM; FPLIST: df40_100p_0d4_22_6x3_38x1_5mm,df40_100p_0d4_22_6x3_38x1_5mm_101_200; Manufacturer: HRS; PN: 320210402
J5 = CM4_CON_B: SMD BTB Male CONN 2*50PIN;L22.6*W3.38*H1.45MM; Manufacturer: HRS; PN: 320210402; Part Type: Connectors; Status: reTerminal DM
J6 = Toggle_Switch_2CH: DIP Toggle Switch;6P; Manufacturer: 德艺隆; Manufacturer Part Number: MK-22D18 G3; PN: 311030004; Part Type: Toggle Switch; Status: reTerminal Plus; Temperature: -20°C to 80°C
MH1-MH4 = MHole: SMD Stud; M2.5铜柱, D5.56*1.5mm, 黄铜, 表面电镀锡(编带包装); Manufacturer: 雄和远景; Manufacturer Part Number: SMTSO2515CTJ; PN: 326050867; Part Type: Mhole; Status: reTerminal DM
R1 R6 R24 R25 R27 R28 = R: SMD RES 22R-5%-1/20W;0201; Manufacturer: YAGEO; Manufacturer Part Number: RC0201JR-0722RL; PN: 301010789; Package Size: 0201; Part Type: RES; Rating: 5%; Status: BeagleBone AI TDA4VM; Temperature: -55°C to 125°C
R26 = R: SMD RES 0R-±1%-1/20W;0201; ASSY: DNP; CLASS: DISCRETE; Company Part Status: BeagleBone Carrier Board; Manufacturer: YAGEO; Manufacturer PN: RC0402JR-070RL; Manufacturer Part Number: RC0201FR-070RL; PN: 301010525; Package Size: 0201; Part Type: RES; Rated Power: 1/16W; Rating: 1%; SIGNAL_MODEL: DEFAULT_RESISTOR_0.001OHM_1_2; Status: BeagleBone AI TDA4VM; Temperature: -55°C to 125°C; Datasheet: Y:\01_Cadence_Library\05_Datasheet\301010000_YAGEO_RC0402JR-070RL_Datasheet.pdf
R29 R48 = R: SMD RES 0R-±1%-1/20W;0201; CLASS: DISCRETE; Company Part Status: BeagleBone Carrier Board; Manufacturer: YAGEO; Manufacturer PN: RC0402JR-070RL; Manufacturer Part Number: RC0201FR-070RL; PN: 301010525; Package Size: 0201; Part Type: RES; Rated Power: 1/16W; Rating: 1%; SIGNAL_MODEL: DEFAULT_RESISTOR_0.001OHM_1_2; Status: BeagleBone AI TDA4VM; Temperature: -55°C to 125°C; Datasheet: Y:\01_Cadence_Library\05_Datasheet\301010000_YAGEO_RC0402JR-070RL_Datasheet.pdf
R30 R31 R177 R178 = R: SMD RES;4.7K-5%-1/20W;0201; CLASS: DISCRETE; Company Part Status: BeagleBone Carrier Board; Manufacturer: YAGEO; Manufacturer PN: RC0402JR-074K7L; Manufacturer Part Number: RC0201JR-074K7L; PN: 301010677; Package Size: 0201; Part Type: RES; Rated Power: 1/16W; Rating: 5%; Status: BeagleV-Ahead; Temperature: -55°C to 125°C
R33 = R: SMD RES 0R-±1%-1/20W;0201; ASSY: DNP; Manufacturer: YAGEO; Manufacturer Part Number: RC0201FR-070RL; PN: 301010525; Package Size: 0201; Part Type: RES; Rating: 1%; Status: BeagleBone AI TDA4VM; Temperature: -55°C to 125°C; Datasheet: Y:\01_Cadence_Library\05_Datasheet\301010000_YAGEO_RC0402JR-070RL_Datasheet.pdf
R34 R44 R50 R573 = R: SMD RES 10K-±1%-1/20W;0201; CLASS: DISCRETE; Company Part Status: BeagleBone Carrier Board; Manufacturer: YAGEO; Manufacturer PN: RC0402JR-0710KL; Manufacturer Part Number: RC0201FR-0710KL; PN: 301010526; Package Size: 0201; Part Type: RES; Rated Power: 1/16W; Rating: 1%; Status: BeagleBone AI TDA4VM; Temperature: -55°C to 125°C
R35 = R: SMD RES 18K-1%-1/16W;0402; CLASS: DISCRETE; Company Part Status: RT-M7; Manufacturer: YAGEO; Manufacturer PN: RC0402FR-0718KL; Manufacturer Part Number: RC0402FR-0718KL; PN: 301011349; Package Size: 0402; Part Type: RES; Rated Power: 1/16W; Rating: 1%; Status: RT-M7; Temperature: -55°C to 155°C
R106 R107 = R: SMD RES 2.2K-1%-1/20W;0201; CLASS: DISCRETE; Company Part Status: BeagleBone Carrier Board; Manufacturer: YAGEO; Manufacturer PN: RC0402FR-074K7L; Manufacturer Part Number: RC0201FR-072K2L; PN: 301010753; Package Size: 0201; Part Type: RES; Rated Power: 1/16W; Rating: 1%; Status: BeagleBone AI TDA4VM; Temperature: -55°C to 125°C
B1 = ACTIVE_BUZZER: PN: 312020803; Part Type: Buzzer; Status: reTerminal Plus
C6 C44 C48 C163 = CC: SMD CAP Ceramic 4.7uF-6.3V-20%-X5R;0402; Manufacturer: YAGEO; Manufacturer Part Number: CC0402MRX5R5BB475; PN: 302010019; Package Size: 0402; Rating: 6.3V,X5R; Status: BeagleBone Carrier Board; Temperature: -55°C to 85°C
D12 = DIODE_TVS_BI-DIR: SMD Diode ESD 0.05pF;0402; Manufacturer: SEMITEL; PN: 304060074; Part Type: TVS; Rating: 5V; Status: BeagleBone Carrier Board; Temperature: -40°C to 90°C
FB27 = FB: SMD Ferrite Bead 120R-1.3A;0402; Manufacturer: Murata; Manufacturer Part Number: BLM15PD121SN1D; PN: 303030040; Package Size: 0402; Rating: 1.3A; Status: BeagleBone Carrier Board; Temperature: -55°C to 125°C
J25 = JST_10+2P: SMD Male 1.0mm; 10P+2P-1.00mm-90D; PN: TMP-564; Package Size: 1.0-10P; Status: reComputer R1002; Temperature: -25°C to 70°C
Q3 = NMOS_123: SMD MOSFET N-CH 60V-300mA ;SOT-23; Manufacturer: NXP; PN: 305030028; Part Type: NMOS; Rating: 60V 300mA; Status: Geni; Temperature: -65°C to 150°C
R38 = R: SMD RES 33R-5%-1/10W;0603; Manufacturer: YAGEO; Manufacturer Part Number: RC0603JR-0733RL; PN: 301010117; Part Type: RES; Rating: 5%; Status: Sensecap Gateway V1; Temperature: -55°C to 155°C
R39 = R: SMD RES 1K-±1%-1/20W;0201; CLASS: DISCRETE; Company Part Status: BeagleBone Carrier Board; Manufacturer: YAGEO; Manufacturer PN: RC0402JR-071KL; Manufacturer Part Number: RC0201FR-071KL; PN: 301010523; Package Size: 0201; Part Type: RES; Rated Power: 1/16W; Rating: 1%; Status: ST; Temperature: -55°C to 125°C
SW1 = BUTTON_2+2P: DIP Button Side 250gf;4P-90D; PN: 311021719; Package Size: 7.3*7.1*5mm; Rating: 160gf; Status: reComputer CM4 R101; Temperature: -25°C to 85°C
U3 = SGM7222: SMD IC Analog Switch;High Speed USB 2.0 (480Mbps) DPDT Analog Switch;WQFN-10; Manufacturer: SGMICRO; PN: 310100627; Part Type: Analog Switch; Priority: A; Status: reComputer Jetson; Temperature: -40°C to 85°C
U20 U24 = SN74LVC2G241: SMD IC Logic;Dual Buffer/Driver With 3-State Outputs;US8(8-VFSOP); Manufacturer: TI; PN: 310050078; Package Size: 8-VFSOP; Status: BeagleBone Carrier Board; Temperature: -40°C to 125°C
C42 = CC: SMD CAP Ceramic 10uF-10V-10%-X5R;0603; CLASS: DISCRETE; Company Part Status: BeagleBone Carrier Board; Dielectric Type: Ceramic; Manufacturer: YAGEO; Manufacturer PN: CC0603KRX5R6BB106; Manufacturer Part Number: CC0603KRX5R6BB106; PN: 302010103; Package Size: 0603; Part Type: Ceramic; Rating: 10V,X5R; Status: BeagleBone Carrier Board; Temperature: -55°C to 85°C; Temperature Coefficient: X5R; Tolerance: 10%
C56 C57 = CC: SMD CAP Ceramic 12pF-50V-1%-NPO;0201; Manufacturer: YAGEO; Manufacturer Part Number: CC0201FRNPO9BN120; PN: 302013026; Package Size: 0201; Status: LR1110; Temperature: -55°C to 125°C
C502 = CC: SMD CAP Ceramic 1uF-10V-10%-X5R;0402; Manufacturer: YAGEO; Manufacturer Part Number: CC0402KRX5R6BB105; PN: 302010040; Part Type: Ceramic; Rating: 10V,X5R; Status: BeagleBone Carrier Board; Temperature: -55°C to 85°C
FB1-FB3 = FB: SMD Ferrite Bead;120R-2A;0603; CLASS: DISCRETE; Company Part Status: BeagleBone Carrier Board; Manufacturer: Murata; Manufacturer PN: BLM18PG121SN1D; Manufacturer Part Number: BLM18PG121SN1D; PN: 303030024; Package Size: 0603; Part Type: Ferrite Bead; Rating: 2A; Status: BeagleBone Carrier Board; Temperature: -55°C to 125°C
R41 R43 = R: SMD RES 10K-±1%-1/20W;0201; CLASS: DISCRETE; Company Part Status: BeagleBone Carrier Board; Manufacturer: YAGEO; Manufacturer PN: RC0402JR-0710KL; Manufacturer Part Number: RC0201FR-0710KL; PN: 301010526; Package Size: 0201; Part Type: RES; Rated Power: 1/16W; Rating: 1%; SIGNAL_MODEL: DEFAULT_RESISTOR_10000OHM_1_2; Status: BeagleBone AI TDA4VM; Temperature: -55°C to 125°C
R45 = R: SMD RES 12.4K-1%-1/16W;0402; Manufacturer: YAGEO; Manufacturer Part Number: RC0402FR-0712K4L; PN: 301011091; Package Size: 0402; Rating: 1%; Status: Seeed BeagleBone Green Gateway; Temperature: -55°C to 155°C
R46 R47 R651 = R: SMD RES 0R-±1%-1/20W;0201; CLASS: DISCRETE; Company Part Status: BeagleBone Carrier Board; Manufacturer: YAGEO; Manufacturer PN: RC0402JR-070RL; Manufacturer Part Number: RC0201FR-070RL; PN: 301010525; Package Size: 0201; Part Type: RES; Rated Power: 1/16W; Rating: 1%; Status: BeagleBone AI TDA4VM; Temperature: -55°C to 125°C; Datasheet: Y:\01_Cadence_Library\05_Datasheet\301010000_YAGEO_RC0402JR-070RL_Datasheet.pdf
R49 = R: SMD RES 1M-5%-1/20W;0201; CLASS: DISCRETE; Company Part Status: BeagleBone Carrier Board; Manufacturer: YAGEO; Manufacturer PN: RC0402FR-071ML; Manufacturer Part Number: RC0201JR-071ML; PN: 301010676; Package Size: 0201; Part Type: RES; Rated Power: 1/16W; Rating: 5%; SIGNAL_MODEL: DEFAULT_RESISTOR_0.001OHM_1_2; Status: BeagleV-Ahead; Temperature: -55°C to 155°C
U4 = LAN9512_4: SMD IC Interface;USB 2.0 Hub and 10/100 Ethernet Controller;QFN-64; Manufacturer: Microchip; PN: 310070815; Package Size: QFN-64; Status: SeeedStudio BeagleBone Green Gateway Baseboard; Temperature: -40°C to 85°C
U33 = FM93C66A: SMD IC Memory;4Kbit Microwire Compatible Serial EEPROM;SOP8; Manufacturer: FM(复旦微); PN: 310091524; Package Size: SOP8; Status: reRouter CM4 PoE; Temperature: -55°C to 125°C
X1 = XTAL_4P: SMD Crystal 25MHz-8pF-10ppm-30R;4P-SMD-L3.2*W2.5*H0.8mm; Manufacturer: Interquip; Manufacturer Part Number: 5YAA25000081TF30Q2; PN: 306011162; Package Size: 3.2x2.5mm; Rating: 10ppm,8pF; Status: RV PI; Temperature: -40°C to 85°C

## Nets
5V_ISO_INPUT: C132.1 L11.1 U23.1(OUT)
5V_ISO_OUT: C134.1 R117.2 R118.1 TP32.1(TP) ; also on sheet 15
5V_TYPC: R32.2 ; also on sheet 11
+1.8V_OUT: C34.2 J4.88(1.8V1) J4.90(1.8V2) ; also on sheet 13
+3.3V_OUT: C32.1 C33.2 J4.84(3.3V1) J4.86(3.3V2) R26.2 R29.2 R181.1
GND: C2.2 C3.2 C6.2 C7.2 C8.2 C9.2 C10.2 C11.2 C12.2 C13.2 C14.2 C15.2 C16.2 C19.2 C20.2 C21.2 C22.2 C23.2 C24.2 C28.2 C29.2 C31.2 C32.2 C33.1 C34.1 C35.1 C36.2 C37.2 C38.2 C40.2 C41.2 C42.2 C43.2 C44.2 C45.2 C46.2 C47.2 C48.2 C49.2 C50.2 C51.2 C52.2 C53.2 C54.2 C55.2 C56.2 C57.2 C130.2 C131.2 C132.2 C133.2 C163.2 C500.2 C501.2 C502.2 C508.2 C509.2 D5.1 D8.1(A) D10.1(A) D11.1(A) D12.1 J1.2 J2.7 J2.8 J2.9 J2.10 J4.1(GND1) J4.2(GND11) J4.7(GND2) J4.8(GND12) J4.13(GND3) J4.14(GND13) J4.22(GND14) J4.23(GND4) J4.32(GND15) J4.33(GND5) J4.42(GND16) J4.43(GND6) J4.52(GND17) J4.53(GND7) J4.59(GND8) J4.60(GND18) J4.65(GND9) J4.66(GND19) J4.71(GND10) J4.74(GND20) J4.98(GND21) J5.107(GND22) J5.108(GND36) J5.113(GND23) J5.114(GND37) J5.119(GND24) J5.120(GND38) J5.125(GND25) J5.126(GND39) J5.131(GND26) J5.132(GND40) J5.137(GND27) J5.138(GND41) J5.144(GND42) J5.150(GND43) J5.155(GND28) J5.156(GND44) J5.161(GND29) J5.162(GND45) J5.167(GND30) J5.168(GND46) J5.173(GND31) J5.174(GND47) J5.179(GND32) J5.180(GND48) J5.185(GND33) J5.186(GND49) J5.191(GND34) J5.192(GND50) J5.197(GND35) J5.198(GND51) J6.1(CH1A) J6.4(CH2B) J25.10 MH1.1(NC) MH2.1(NC) MH3.1(NC) MH4.1(NC) Q3.2(S) R7.2 R10.1 R12.2 R14.2 R17.1 R19.2 R21.2 R35.2 R37.2 R40.2 R42.1 R45.1 R48.2 R119.2 R120.2 R123.1 R183.2 R573.2 R651.1 SW1.1 SW1.3 SW1.4 TP2.1(TP) TP3.1(TP) TP4.1(TP) TP5.1(TP) TP6.1(TP) TP7.1(TP) TP8.1(TP) TP9.1(TP) TP13.1(TP) TP17.1(TP) U1.7(GND) U1.9(E-PAD) U2.7(GND) U2.9(E-PAD) U3.4(GND) U4.29(TMS) U4.30(TDI) U4.32(TCK) U4.34(TEST2) U4.65(VSS(FLAG)) U20.1(~{1OE}) U20.4(GND) U22.1(VIN-) U23.2(GND) U24.1(~{1OE}) U24.4(GND) U33.5(GND) X1.2 X1.4 ; also on sheet 9 10 11 12 13 14 15 16 18
GND_EARTH: G1.1 J3.1 J3.2 J3.3 J3.4 J25.S1 J25.S2 MH11.1(NC) MH12.1(NC) MH13.1(NC) MH14.1(NC) ; also on sheet 9 10 11 14 18
GND_ISO: C134.2 D34.1(A) R123.2 U22.3(VOUT-) ; also on sheet 15
VDD18CORE: C6.1 C14.1 C19.1 U4.15(VDD18CORE) U4.38(VDD18CORE)
VDD18ETHPLL: C502.1 FB3.1 U4.48(VDD18ETHPLL)
VDD18USBPLL: C501.1 FB3.2 U4.62(VDD18USBPLL)
VDD33_HUB1: C40.1 C41.1 C43.1 C44.1 C45.1 C46.1 C47.1 C500.1 FB1.2 FB2.1 R41.1 R43.1 R44.1 R50.2 U4.19(VDD33IO) U4.27(VDD33IO) U4.33(VDD33IO) U4.39(VDD33IO) U4.46(VDD33IO) U33.8(VCC) ; also on sheet 18
VDD33_HUB2: U4.40(TEST3) ; also on sheet 9
VDD33A_HUB1: C48.1 C49.1 C50.1 C51.1 C52.1 C53.1 C54.1 FB2.2 U4.5(VDD33A) U4.10(VDD33A) U4.49(VDD33A) U4.51(VDD33A) U4.54(VDD33A) U4.57(VDD33A) U4.64(VDD33A)
VDD_3V3_SYS: C13.1 C23.1 C24.1 C30.1 C38.1 C42.1 C163.1 C508.1 C509.1 FB1.1 FB27.2 L3.2 R38.1 R653.1 R654.1 TP11.1(TP) U3.9(VCC) U20.7(2OE) U20.8(VCC) U24.7(2OE) U24.8(VCC) ; also on sheet 9 10 11 12 13 14 15 16 18
VDD_5V_SYS: C10.1 C11.1 C12.1 C17.1 C31.1 C130.1 C131.1 J4.77(5V1) J4.79(5V2) J4.81(5V3) J4.83(5V4) J4.85(5V5) J4.87(5V6) L2.2 R33.2 R652.1 TP10.1(TP) U23.5(IN) ; also on sheet 9 10 12
VDD_IN: C7.1 C8.1 C9.1 C20.1 C21.1 C22.1 D2.2(C) J2.2 J2.4 J2.6 R8.1 R16.1 TP1.1(TP) U1.2(VIN) U2.2(VIN)
VDD_UPS: D2.1(A) J2.1 J2.3 J2.5 Q1.5(D1) Q1.6(D2) Q1.7(D3) Q1.8(D4) Q1.9(D5)
Buzzer_EN: R39.1 ; also on sheet 18
CAM0_C_N: J5.140(CAM0_C_N) ; also on sheet 10
CAM0_C_P: J5.142(CAM0_C_P) ; also on sheet 10
CAM0_D0_N: J5.128(CAM0_D0_N) ; also on sheet 10
CAM0_D0_P: J5.130(CAM0_D0_P) ; also on sheet 10
CAM0_D1_N: J5.134(CAM0_D1_N) ; also on sheet 10
CAM0_D1_P: J5.136(CAM0_D1_P) ; also on sheet 10
CAM_GPIO: J4.97(Camera_GPlO) ; also on sheet 10
CM4_GPIO16: J4.29(GPIO16) ; also on sheet 15
CM4_GPIO17: J4.50(GPIO17) ; also on sheet 15
CM4_GPIO_VREF: C35.2 J4.78(GPIO_VREF(1.8v/3.3v_Input)) R29.1 R30.1 R31.1 R106.1 R107.1 R177.1 R178.1 TP16.1(TP)
CM4_IIC0_SCL: J4.35(ID_SC) R177.2 ; also on sheet 10
CM4_IIC0_SDA: J4.36(ID_SD) R178.2 ; also on sheet 10
CM4_IIC1_SCL: R27.1 R30.2 ; also on sheet 12
CM4_IIC1_SDA: R28.1 R31.2 ; also on sheet 12
CM4_IIC3_SCL: R24.1 ; also on sheet 13 15 18
CM4_IIC3_SDA: R25.1 ; also on sheet 13 15 18
CM4_IIC5_SCL: J2.11 R6.1 R106.2 ; also on sheet 12
CM4_IIC5_SDA: J2.13 R1.2 R107.2 ; also on sheet 12
CM4_IN1: J4.49(GPIO18) U20.2(1A) ; also on sheet 15
CM4_IN1_LED: J25.7 U20.6(1Y)
CM4_IN2: J4.26(GPIO19) U20.5(2A) ; also on sheet 15
CM4_IN2_LED: J25.8 U20.3(2Y)
CM4_IO_INT: J4.54(GPIO4) ; also on sheet 18
CM4_OUT1: J4.27(GPIO20) U24.2(1A) ; also on sheet 15
CM4_OUT1_LED: U24.6(1Y) ; also on sheet 15
CM4_OUT2: J4.25(GPIO21) U24.5(2A) ; also on sheet 15
CM4_OUT2_LED: U24.3(2Y) ; also on sheet 15
CM4_SDIO_CLK: J4.46(GPIO22) ; also on sheet 15
CM4_SDIO_CMD: J4.47(GPIO23) ; also on sheet 15
CM4_SDIO_DATA0: J4.45(GPIO24) ; also on sheet 15
CM4_SDIO_DATA1: J4.41(GPIO25) ; also on sheet 15
CM4_SDIO_DATA2: J4.24(GPIO26) ; also on sheet 15
CM4_SDIO_DATA3: J4.48(GPIO27) ; also on sheet 15
CM4_SPI0_CE0: J4.39(GPIO8) ; also on sheet 12
CM4_SPI0_CE1: J4.37(GPIO7) ; also on sheet 13
CM4_SPI0_MISO: J4.40(GPIO9) ; also on sheet 12 13
CM4_SPI0_MOSI: J4.44(GPIO10) ; also on sheet 12 13
CM4_SPI0_SCLK: J4.38(GPIO11) ; also on sheet 12 13
CM4_TPM_IRQ: J4.34(GPIO5) ; also on sheet 12
CM4_UART0_RXD: J4.51(GPIO15) ; also on sheet 11
CM4_UART0_TXD: J4.55(GPIO14) ; also on sheet 11
CM4_UPS_DET: J2.12 J4.30(GPIO6) R654.2
EECLK: U4.23(EECLK) U33.2(SK)
EECS: R573.1 U4.24(EECS) U33.1(CS)
EEDI: U4.26(EEDI) U33.4(DO)
EEDO: U4.25(EEDO) U33.3(DI)
Ethernet_LED2: J4.17(Ethernet_nLED2(3.3v)) ; also on sheet 14
Ethernet_LED3: J4.15(Ethernet_nLED3(3.3v)) ; also on sheet 14
Ethernet_Pair0_N: J4.10(Ethernet_Pair0_N) ; also on sheet 14
Ethernet_Pair0_P: J4.12(Ethernet_Pair0_P) ; also on sheet 14
Ethernet_Pair1_N: J4.6(Ethernet_Pair1_N) ; also on sheet 14
Ethernet_Pair1_P: J4.4(Ethernet_Pair1_P) ; also on sheet 14
Ethernet_Pair2_N: J4.9(Ethernet_Pair2_N) ; also on sheet 14
Ethernet_Pair2_P: J4.11(Ethernet_Pair2_P) ; also on sheet 14
Ethernet_Pair3_N: J4.5(Ethernet_Pair3_N) ; also on sheet 14
Ethernet_Pair3_P: J4.3(Ethernet_Pair3_P) ; also on sheet 14
Ethernet_RX_N: U4.53(RXN) ; also on sheet 18
Ethernet_RX_P: U4.52(RXP) ; also on sheet 18
Ethernet_TX_N: U4.56(TXN) ; also on sheet 18
Ethernet_TX_P: U4.55(TXP) ; also on sheet 18
EXT_VCC_9_36V: C1.1 C2.1 D1.2(C) D3.2(C) Q1.1(S1) Q1.2(S2) Q1.3(S3) Q2.2(E) R2.1 R3.1 R4.1
GLOBAL_EN: J4.99(GlobaL_EN) ; also on sheet 12
HDMI0_CEC: J5.151(HDMI0_CEC) ; also on sheet 10
HDMI0_CLK_N: J5.190(HDMI0_CLK_N) ; also on sheet 10
HDMI0_CLK_P: J5.188(HDMI0_CLK_P) ; also on sheet 10
HDMI0_HOTPLUG: J5.153(HDMI0_HOTPLUG) ; also on sheet 10
HDMI0_SCL: J5.200(HDMI0_SCL) ; also on sheet 10
HDMI0_SDA: J5.199(HDMI0_SDA) ; also on sheet 10
HDMI0_TX0_N: J5.184(HDMI0_TX0_N) ; also on sheet 10
HDMI0_TX0_P: J5.182(HDMI0_TX0_P) ; also on sheet 10
HDMI0_TX1_N: J5.178(HDMI0_TX1_N) ; also on sheet 10
HDMI0_TX1_P: J5.176(HDMI0_TX1_P) ; also on sheet 10
HDMI0_TX2_N: J5.172(HDMI0_TX2_N) ; also on sheet 10
HDMI0_TX2_P: J5.170(HDMI0_TX2_P) ; also on sheet 10
ISO_5V: R117.1 U22.4(VOUT+)
LTE_LED_WWAN#: J25.6 ; also on sheet 13
nEXTRST: J4.100(nEXTRST) R46.1
nLNKA_LED: U4.21(nLNKA_LED/GPIO1) ; also on sheet 18
nPIBOOT: J4.93(nRPIBOOT) J6.2(COM1)
nPWR_LED: J4.95(nPL_LED_PWR) J25.1
nSPD_LED: U4.22(nSPD_LED/GPIO2) ; also on sheet 18
PCIE_CLK_N: J5.112(PCle_CLK_N) ; also on sheet 16
PCIE_CLK_NREQ: J5.102(PCle_CLK__nREQ) ; also on sheet 16
PCIE_CLK_P: J5.110(PCle_CLK_P) ; also on sheet 16
PCIE_nRST: J5.109(PCle_nRST) ; also on sheet 16
PCIE_RX_N: J5.118(PCle__RX_N) ; also on sheet 16
PCIE_RX_P: J5.116(PCle_RX_P) ; also on sheet 16
PCIE_TX_N: J5.124(PCle_TX_N) ; also on sheet 16
PCIE_TX_P: J5.122(PCle_TX_P) ; also on sheet 16
PL_nLED: J4.21(PL_nLED_Activity) J25.2
PoE_12V: D1.1(A) ; also on sheet 14
RS485_POWER_EN: R122.1 ; also on sheet 18
RUN_PG: J4.92(RUN_PG) R36.2
SD_VDD_Override: J4.73(SD_VDD_Override) R26.1
USB1_RST: C55.1 R44.2 R46.2 U4.12(n_RESET) ; also on sheet 9
USB_0M: U3.7(D1-) U4.58(USBDM0)
USB_0P: U3.1(D1+) U4.59(USBDP0)
USB_1M: U3.6(D2-) ; also on sheet 11
USB_1P: U3.2(D2+) ; also on sheet 11
USB_DM: J5.103(USB2_N) U3.5(D-)
USB_DP: J5.105(USB2_P) U3.3(D+)
USB_HUB1_DM2: U4.1(USBDM2) ; also on sheet 15
USB_HUB1_DM3: U4.3(USBDM3) ; also on sheet 9
USB_HUB1_DP2: U4.2(USBDP2) ; also on sheet 15
USB_HUB1_DP3: U4.4(USBDP3) ; also on sheet 9
USB_OTG_ID: C37.1 J5.101(USB_OTG_ID) R34.2 R35.1 U3.10(S) ; also on sheet 11
USB_OTG_ID1: J6.5(COM2) R34.1
USR_LED_B: J25.5 ; also on sheet 18
USR_LED_G: J25.4 ; also on sheet 18
USR_LED_R: J25.3 ; also on sheet 18
N17790840: J4.89(WL_nDisable) TP14.1(TP)
N17790854: J4.91(BT_nDisable) TP15.1(TP)
N18106868: J4.19(Ethernet_nLED1(3.3v)) TP12.1(TP)
N21116206: F1.1 J1.1 R182.1
N21116390: D3.1(A) D5.2 F1.2
N21187983: D8.2(C) R2.2 R5.1
N21187993: Q2.1(B) R5.2
N21188161: D9.1(A) Q2.3(C)
N21188625: C1.2 D9.2(C) Q1.4(G) R3.2 R7.1
N21392725: C36.1 J6.6(CH2A) R32.1 R33.1
N21629438: C3.1 R4.2
N21664516: R37.1 U3.8(~{OE})
N21767500: J4.56(GPIO3) R24.2
N21767503: J4.58(GPIO2) R25.2
N21891930: C56.1 R47.1 R49.1 X1.1
N21894342: C57.1 R49.2 U4.60(XO) X1.3
N23370571: R41.2 U4.11(VBUS_DET)
N23400557: R42.2 U4.63(USBRBIAS)
N23401903: R43.2 U4.41(AUTOMDIX_EN)
N23402124: R45.2 U4.50(EXRES)
N23405519: R47.2 U4.61(XI)
N23455465: D12.2 R36.1 SW1.2
N23459666: R50.1 U4.28(nTRST)
N23461225: R48.1 U4.44(CLK24_EN)
N23461314: TP19.1(TP) U4.45(CLK24_OUT)
N23463479: TP18.1(TP) U4.20(nFDX_LED/GPIO0)
N23473877: B1.1(+) D13.2(C) R38.2
N23473909: B1.2(-) D13.1(A) Q3.3(D)
N23473945: Q3.1(G) R39.2 R40.1
N23529653: J4.80(SCL0) R27.2
N23529656: J4.82(SDA0) R28.2
N23611485: R12.1 U1.4(RT/SYNC)
N23611490: C15.1 U1.6(SS)
N23612078: C5.1 U1.1(BOOT)
N23612081: C5.2 R9.1
N23613464: D10.2(C) L2.1 R9.2 R11.1 U1.8(SW)
N23613978: R8.2 R10.2 U1.3(EN)
N23614867: C17.2 R13.2 R14.1 U1.5(FB)
N23615765: C16.1 R11.2
N23616333: C18.1 U2.1(BOOT)
N23616335: C18.2 R15.1
N23616337: D11.2(C) L3.1 R15.2 R18.1 U2.8(SW)
N23616378: R16.2 R17.2 R181.2 U2.3(EN)
N23616505: R19.1 U2.4(RT/SYNC)
N23616509: C30.2 R20.2 R21.1 U2.5(FB)
N23616593: C28.1 U2.6(SS)
N23616615: C29.1 R18.2
N23763799: G1.2 R182.2 R183.1
N23781625: R651.2 U33.6(ORG)
N23800931: R13.1 R652.2
N23801005: R20.1 R653.2
N23953873: J4.28(GPIO13) R6.2
N23953904: J4.31(GPIO12) R1.1
N23955153: FB27.1 J25.9
N23982561: C133.1 L11.2 U22.2(VIN+)
N23982687: R119.1 R122.2 U23.4(EN)
N23982695: R120.1 U23.3(ISET)
N23982720: D34.2(C) R118.2 TP33.1(TP)

Not connected (* = marked no-connect by the designer): J4 16(Ethernet_SYNC_IN(1.8v))* 18(Ethernet_SYNC_OUT(1.8v))* 20(EEPROM_nWP)* 57(SD_CLK)* 61(SD_DAT3)* 62(SD_CMD)* 63(SD_DAT0)* 64(SD_DAT5)* 67(SD_DAT1)* 68(SD_DAT4)* 69(SD_DAT2)* 70(SD_DAT7)* 72(SD_DAT6)* 75(SD_PWR_ON)* 76(Reserved)* 94(AnaloglP1)* 96(AnaloglP0)*; J5 104(Reserved1)* 106(Reserved2)* 111(VDAC_COMP)* 115(CAM1_D0_N)* 117(CAM1_D0_P)* 121(CAM1_D1_N)* 123(CAM1_D1_P)* 127(CAM1_C_N)* 129(CAM1_C_P)* 133(CAM1_D2_N)* 135(CAM1_D2_P)* 139(CAM1_D3_N)* 141(CAM1_D3_P)* 143(HDMI1_HOTPLUG)* 145(HDMI1_SDA)* 146(HDMI1_TX2_P)* 147(HDMI1_SCL)* 148(HDMI1_TX2_N)* 149(HDMI1_CEC)* 152(HDMI1_TX1_P)* 154(HDMI1_TX1_N)* 157(DSI0_D0_N)* 158(HDMI1_TX0_P)* 159(DSI0_D0_P)* 160(HDMI1_TX0_N)* 163(DSI0_D1_N)* 164(HDMI1_CLK_P)* 165(DSI0_D1_P)* 166(HDMI1_CLK_N)* 169(DSI0_C_N)* 171(DSI0_C_P)* 175(DSI1_D0_N)* 177(DSI1_D0_P)* 181(DSI1_D1_N)* 183(DSI1_D1_P)* 187(DSI1_C_N)* 189(DSI1_C_P)* 193(DSI1_D2_N)* 194(DSI1_D3_N)* 195(DSI1_D2_P)* 196(DSI1_D3_P)*; J6 3(CH1B)*; U4 6(NC/USBDM4)* 7(NC/USBDP4)* 8(NC/USBDM5)* 9(NC/USBDP5)* 13(TEST1)* 14(PRTCTL2)* 16(PRTCTL3)* 17(NC/PRTCTL4)* 18(NC/PRTCTL5)* 31(TDO)* 35(GPIO3)* 36(GPIO4)* 37(GPIO5)* 42(GPIO6)* 43(GPIO7)* 47(TEST4)*; U33 7(NC)*

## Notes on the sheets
sheet 4
- Design Note:
- Imax=1.1A
- PoE PD : 12V@1.1A
- Design Note:
- Main Power Input:
  DC9V - 36V
- L
- Imax=3A
- N
- PE
- Design Note:
- Design Note:
- Design Note:
- D8 :  38.22V - 39.78V
- D5 : Vbr : 44.4 - 49.1V
          Vc : 64.5V
- Overvoltage protection
  VDS:60V
- OVP MAX : 39.78V
- UPS Connector
- Design Note:
- Connect PE
sheet 5
- 9~36V to 5V
- Imax=3A
- 500KHz
- Vout = Vfb x (1 + R13/ R14)
- = 0.75V x (1 + 68K / 12K)
- = 0.75V x 6.66
- = 5V
- Imax=3A
- 9~36V to 3V3
- 500KHz
- Vout = Vfb x (1 + R20/ R21)
- = 0.75V x (1 + 68K / 20K)
- = 0.75V x 4.4
- = 3.3V
- Imax=500mA
- Isolated DCDC 5V to 5V
- Imax=6800/Rset=6800/15000=453mA
sheet 6
- CM4 Core Board Interface 200PIN
- Layout Note:
- CM4 Power：5V@3A
- USB  UBOOT  KEY
- Design Note:
- CM4 Patch Nut
- USB_OTG_ID
- Function
- USB HUB : ENABLE
  TYPE C : DEBUG
- 0 (default)
- USB HUB : DISABLE
  TYPE C : DOWNLOAD
- 1
sheet 7
- Reset Button
- USB 2.0 physical toggle switch
- USB HUB
- USB TYPE-C SWITCH
- USB_OTG_ID
- Function
- 0
- HUB
- 1
- TYPE-C
- LED Connector
- Design Note:
- LED Connector
- BUZZER
sheet 8
- USB_HUB  POWER
- Imax=500mA
- Layout Note:
- ALL USB Signals ：90R
- USB2.0_HUB1 & 100M Ethernet
